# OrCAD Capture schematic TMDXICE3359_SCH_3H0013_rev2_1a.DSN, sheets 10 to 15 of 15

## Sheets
10 P04_AM335x Sheet 2 of 3: size C
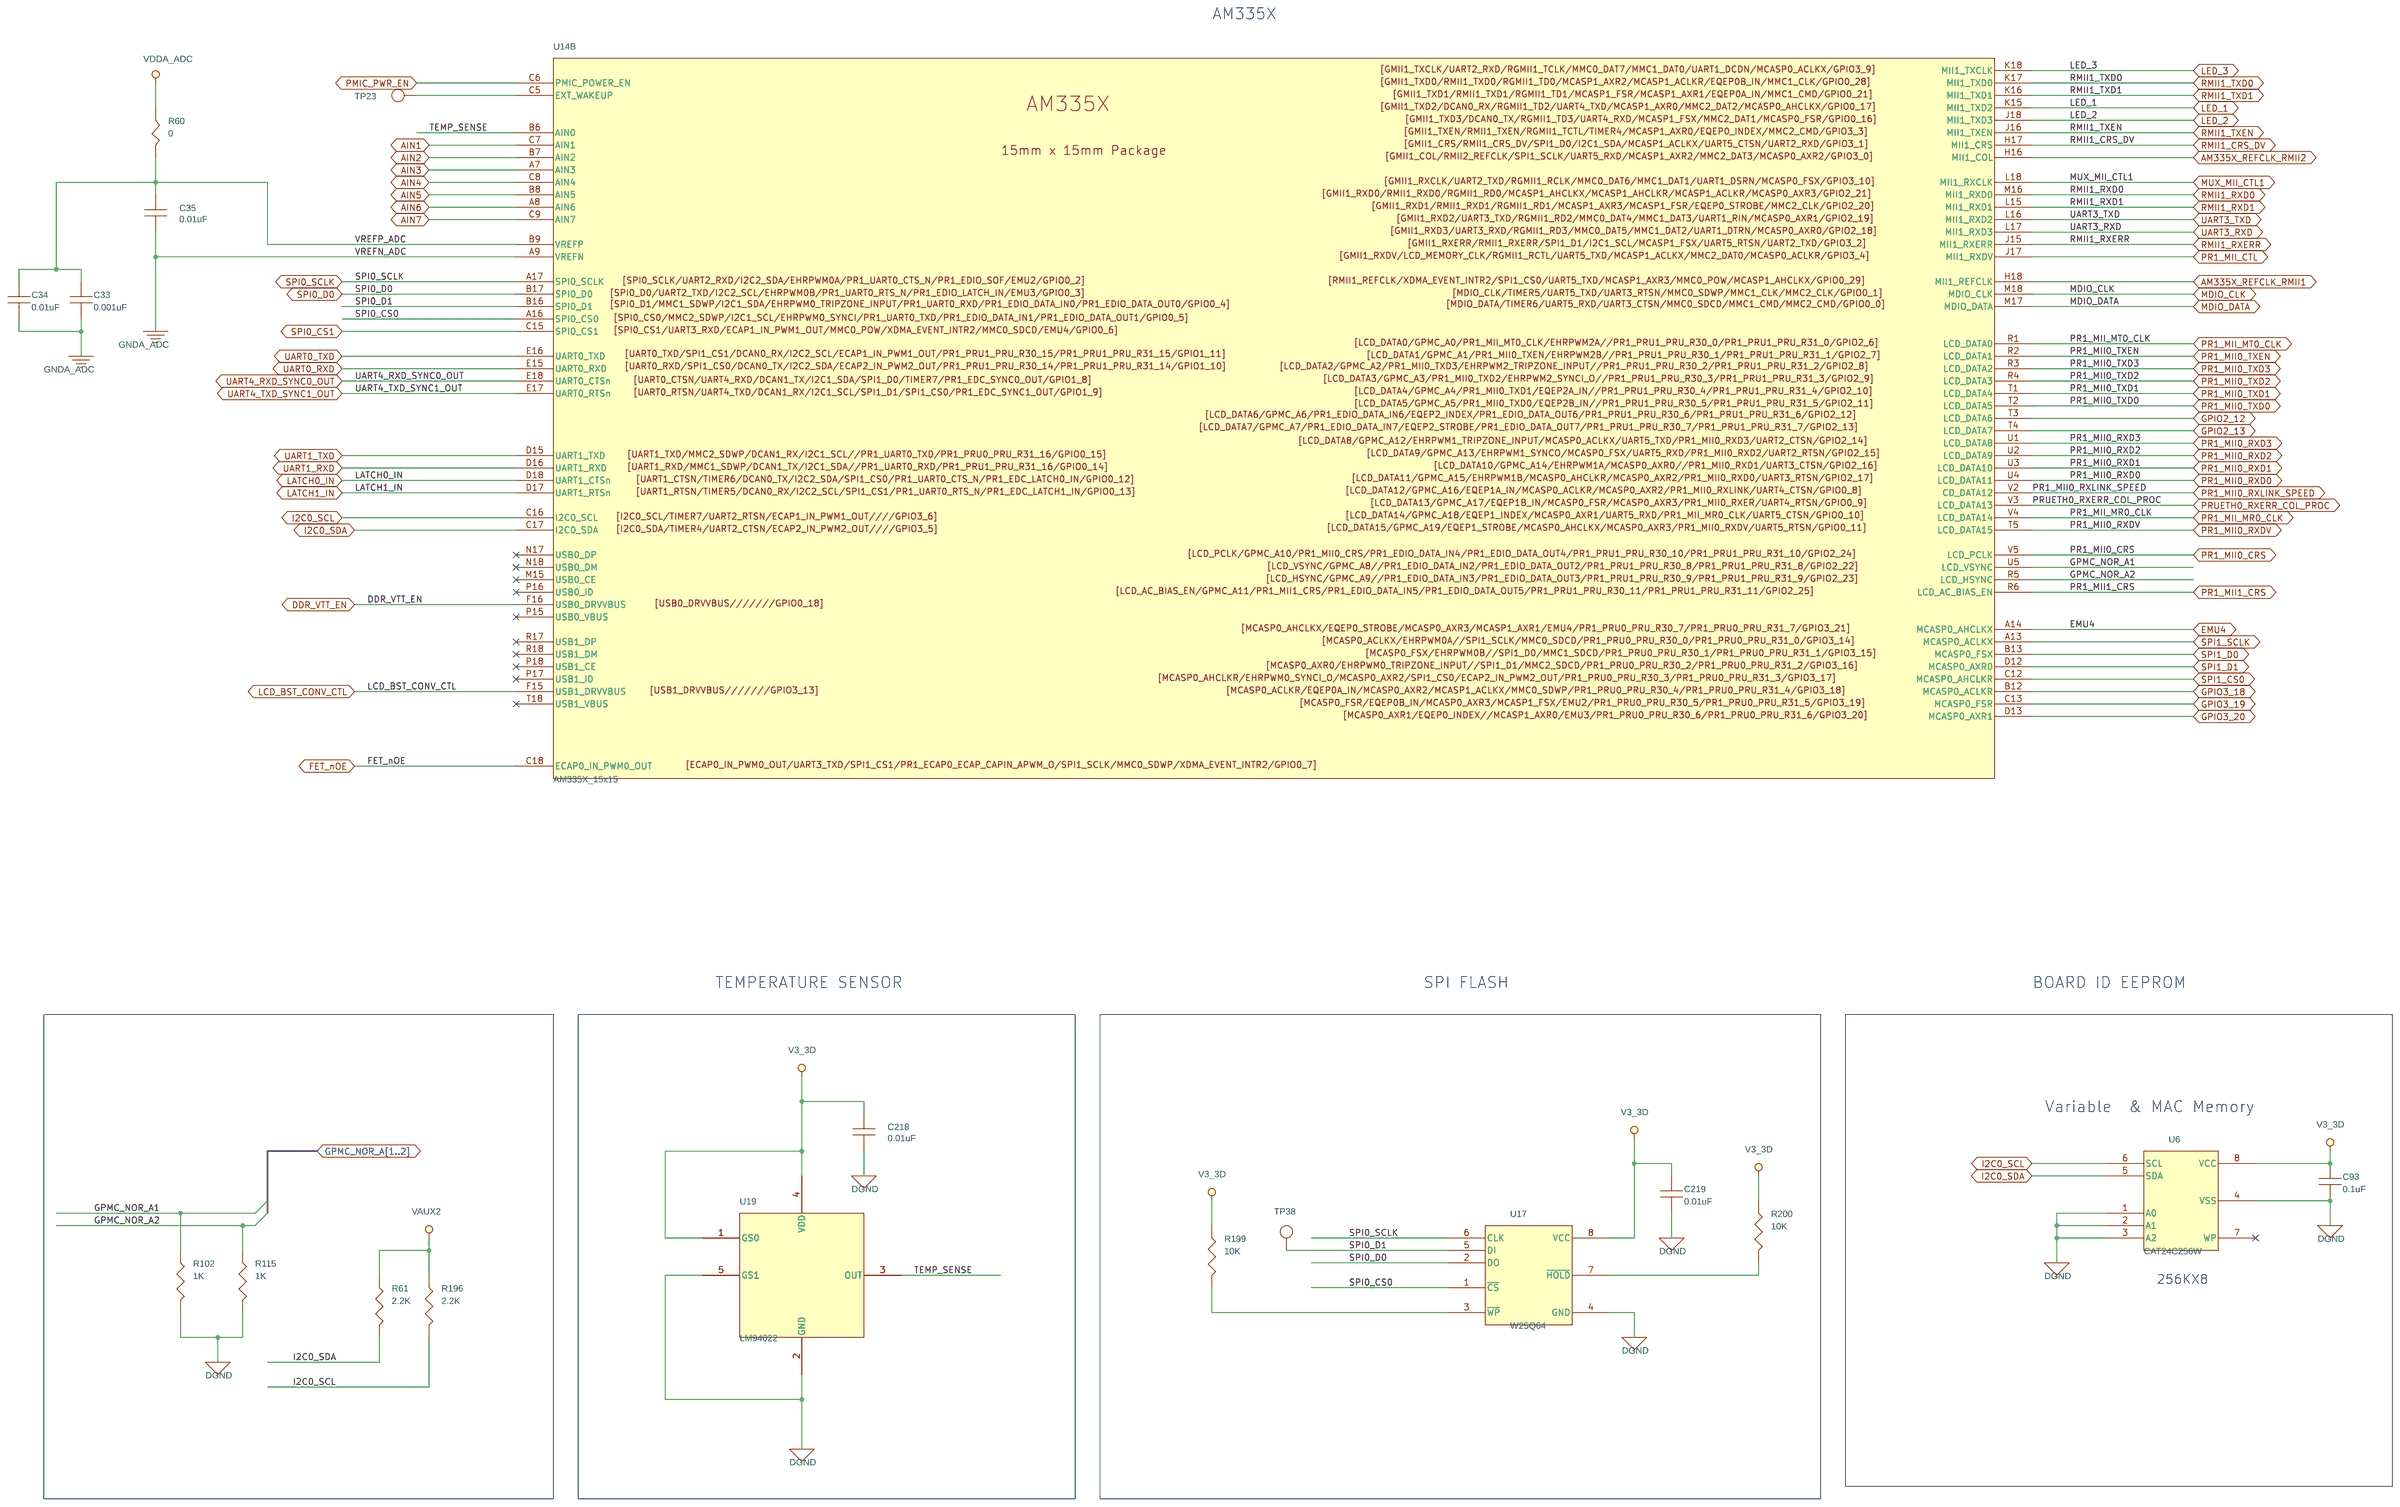
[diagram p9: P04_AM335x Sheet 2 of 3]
11 P03_AM335x Sheet 1 of 3: size C
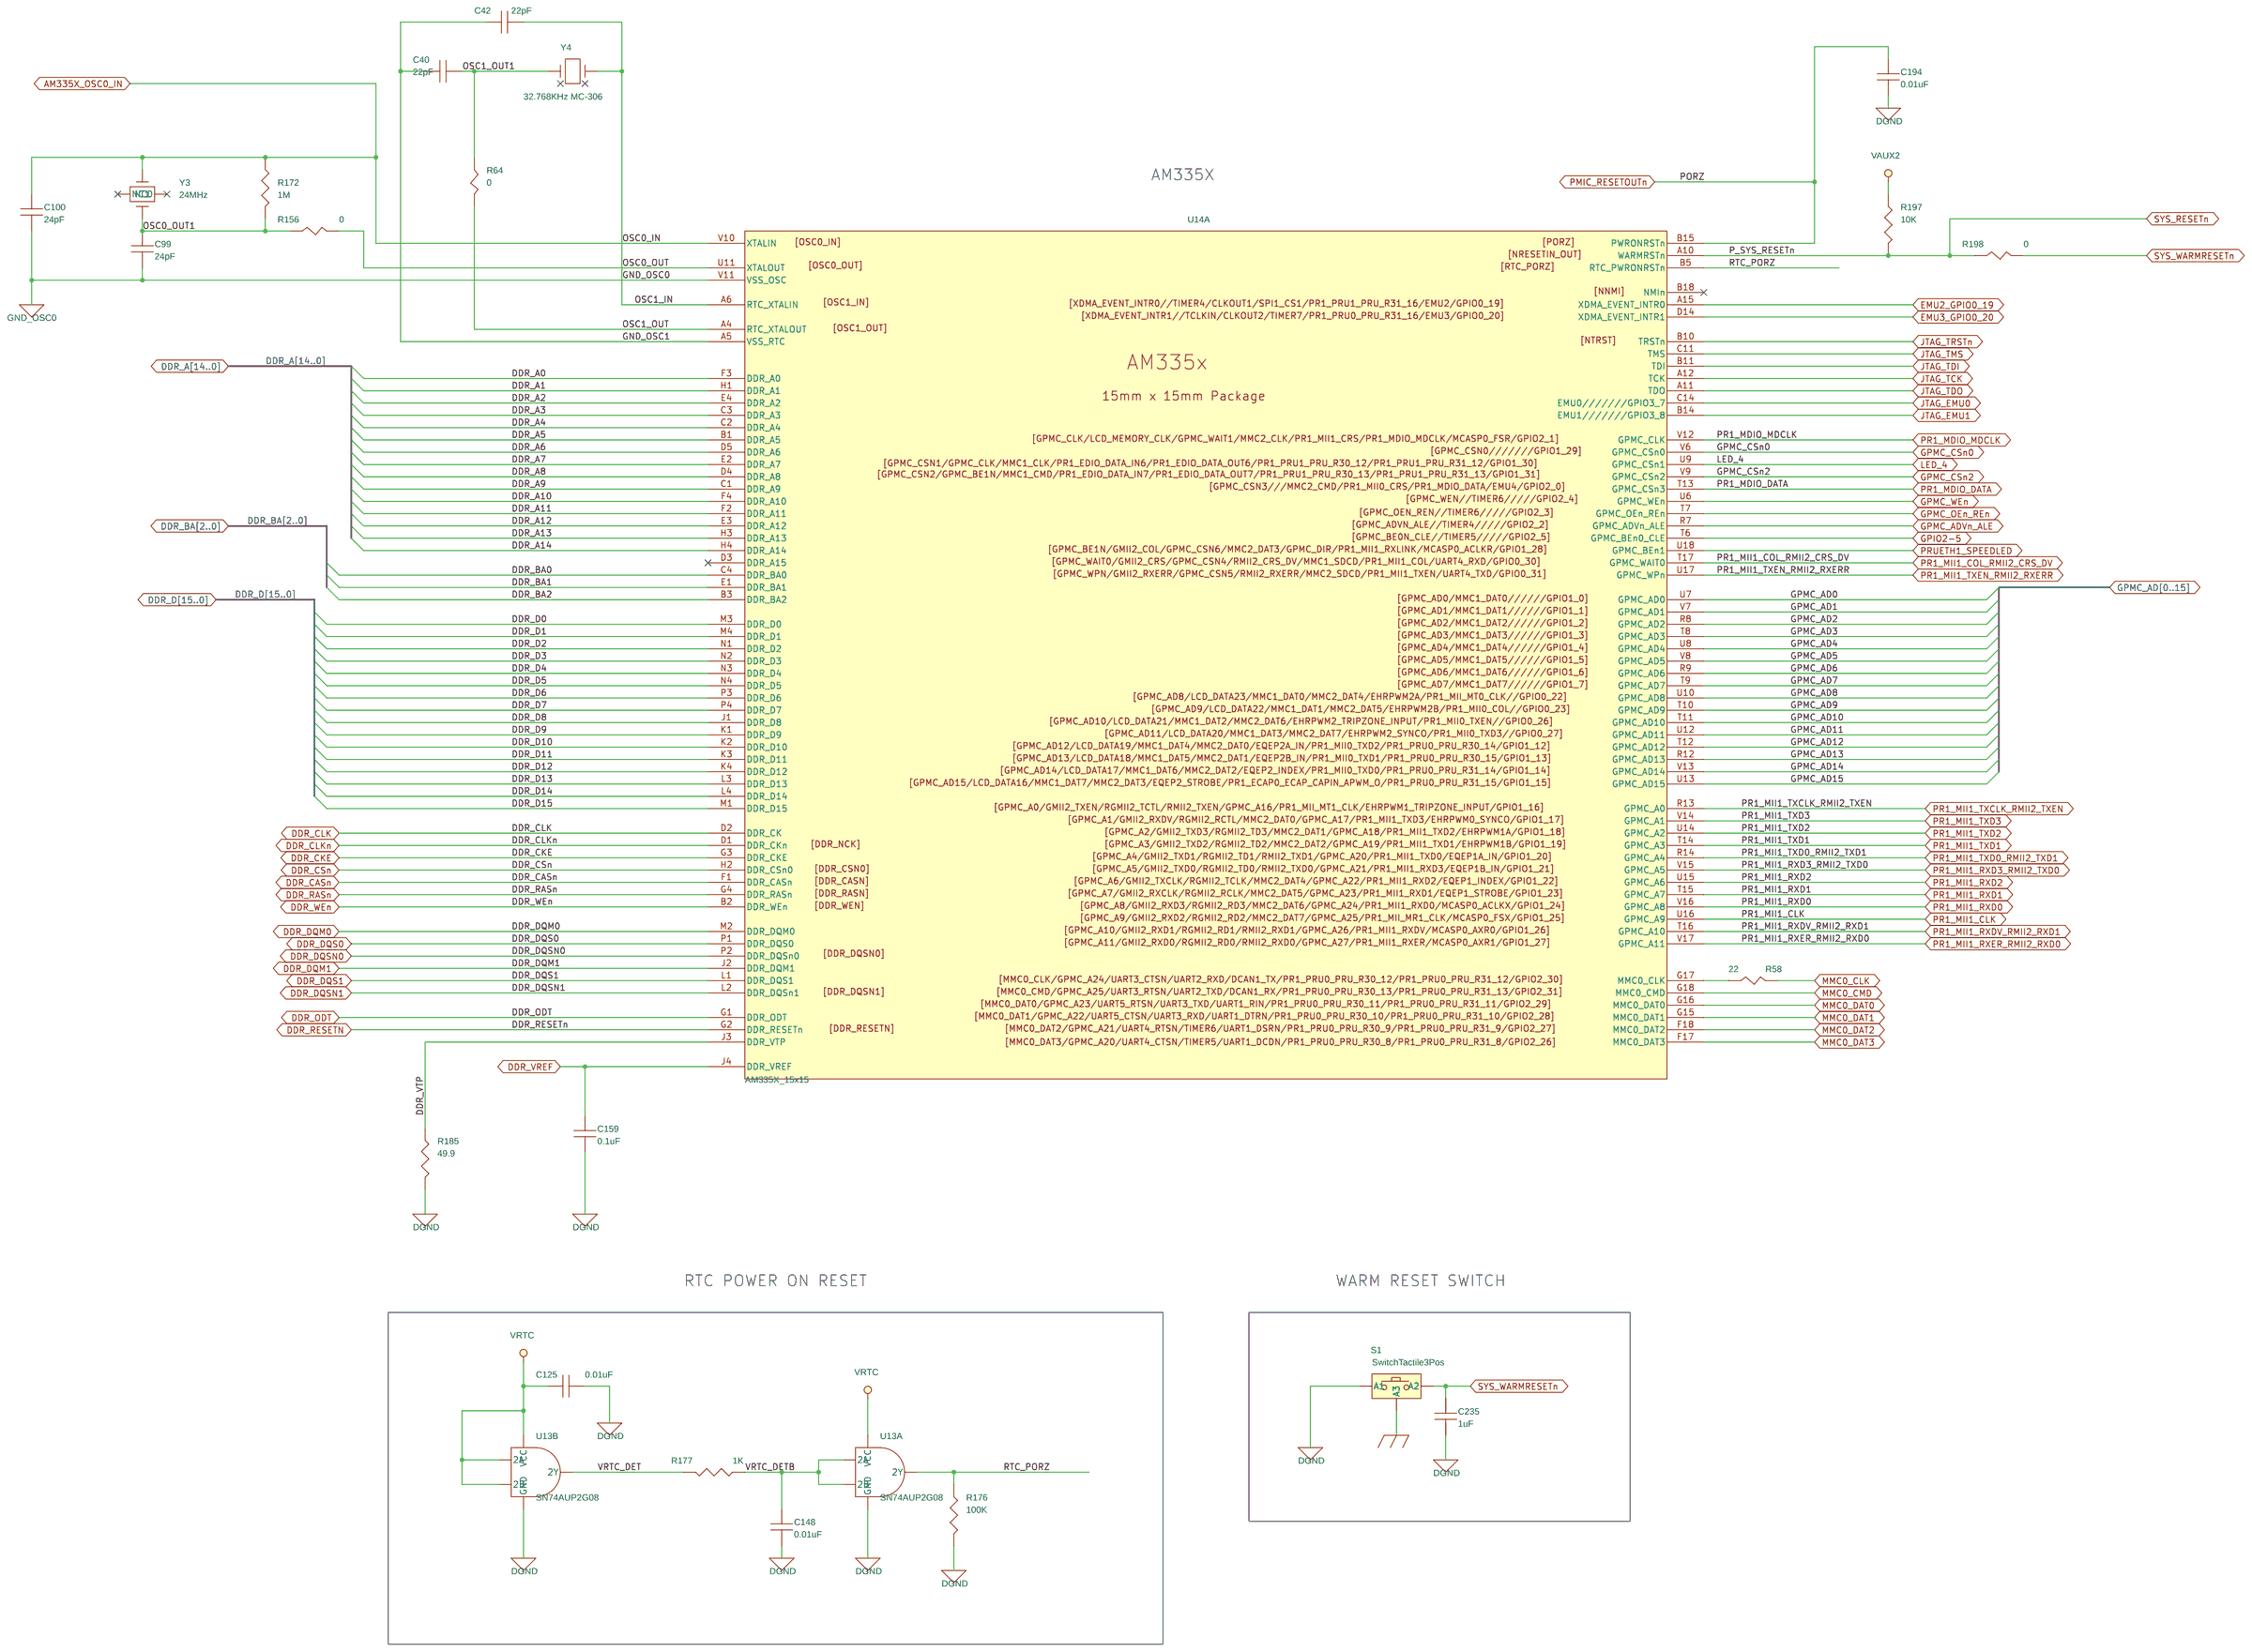
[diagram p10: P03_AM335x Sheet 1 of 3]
12 P02_Power Management: size C
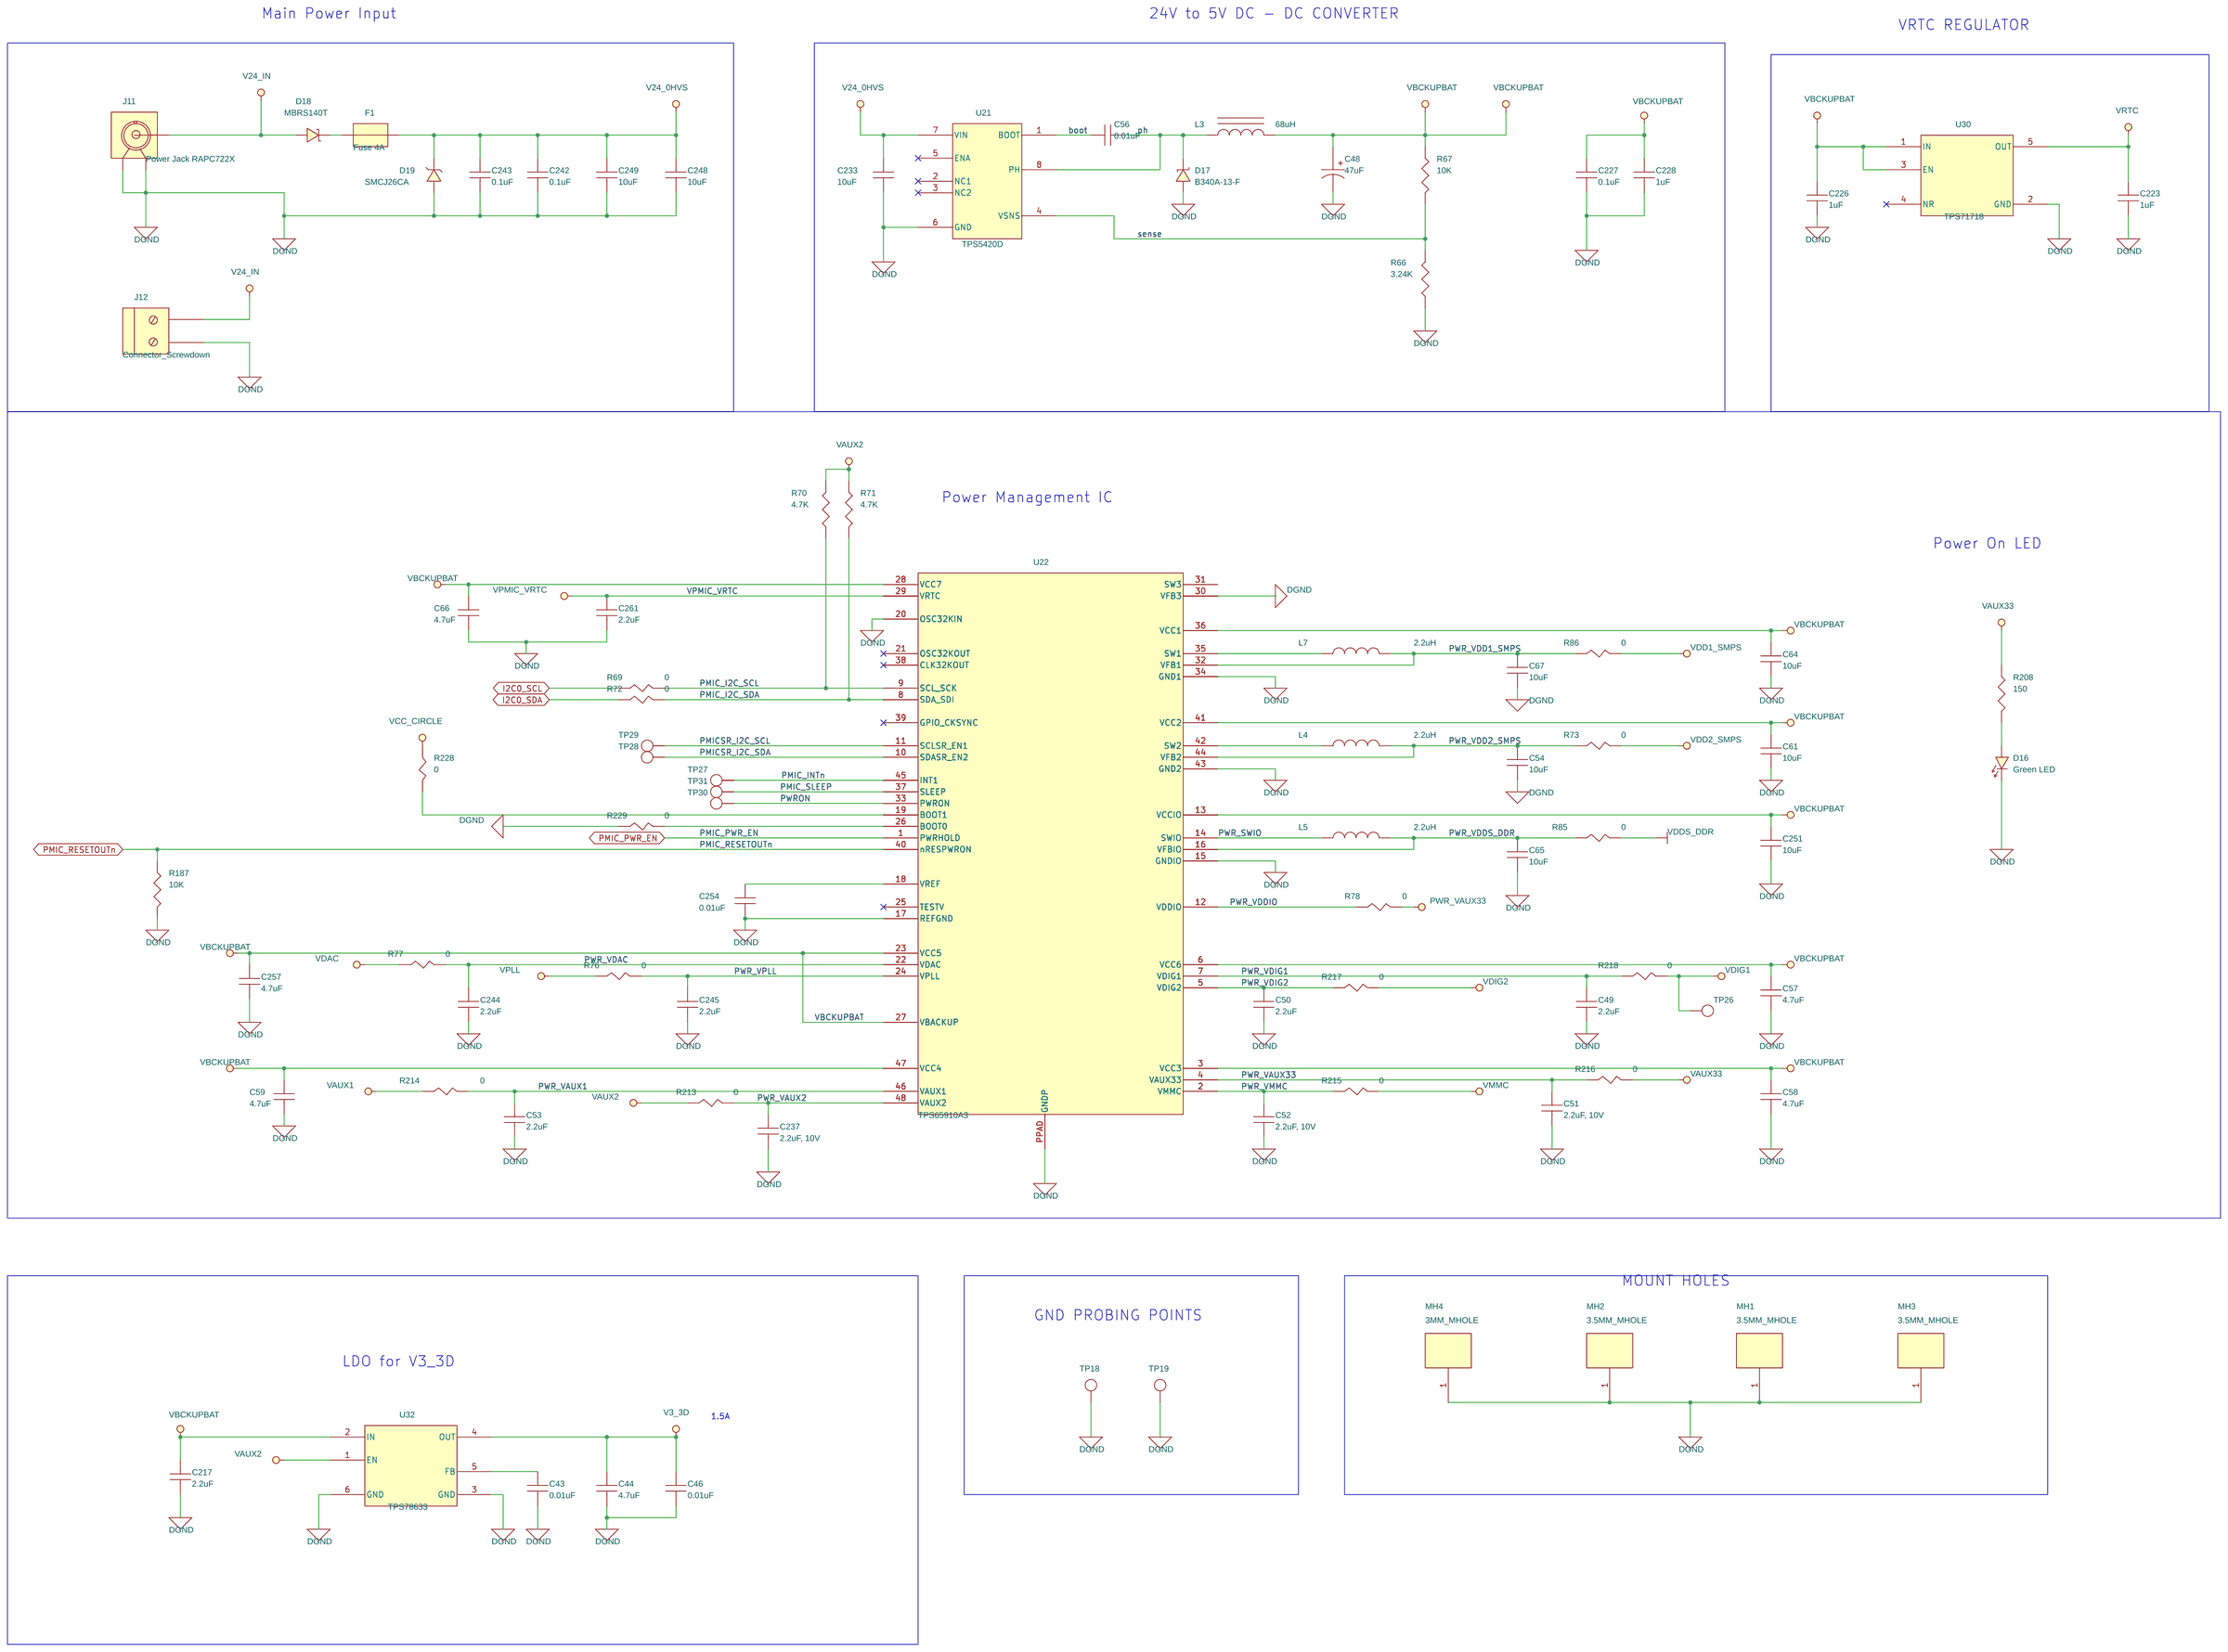
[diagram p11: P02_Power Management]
13 P01_Title Page
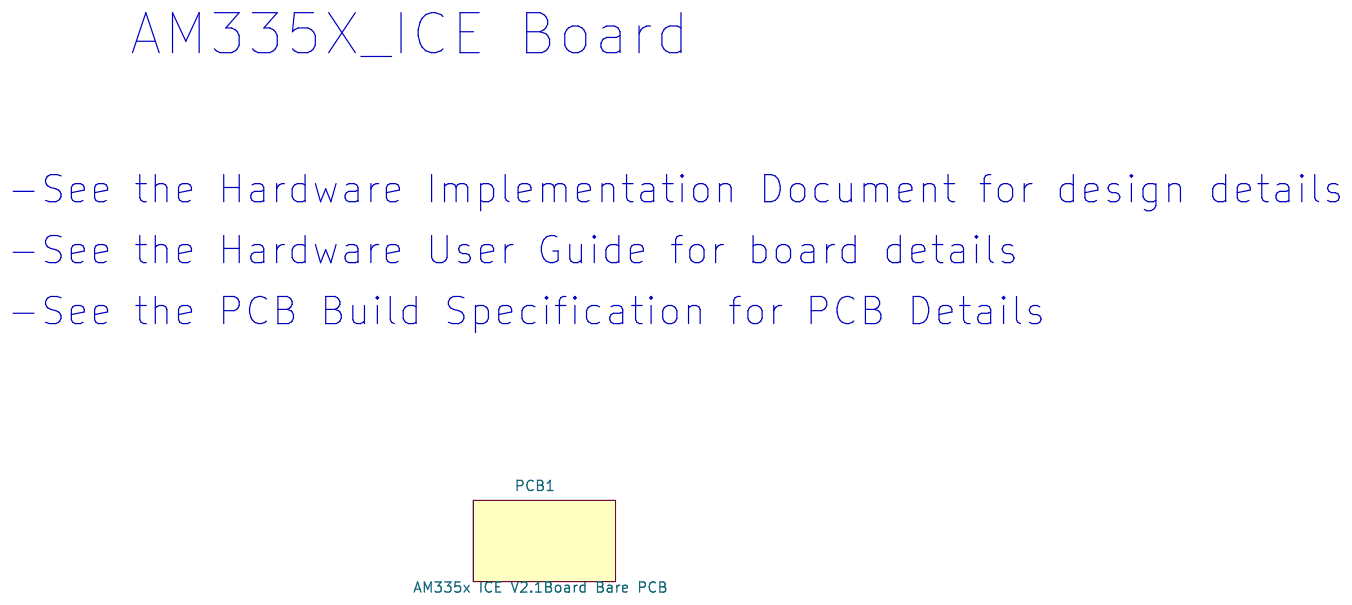
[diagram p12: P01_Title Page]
14 P15_USB_TO_UART/ JTAG: size C
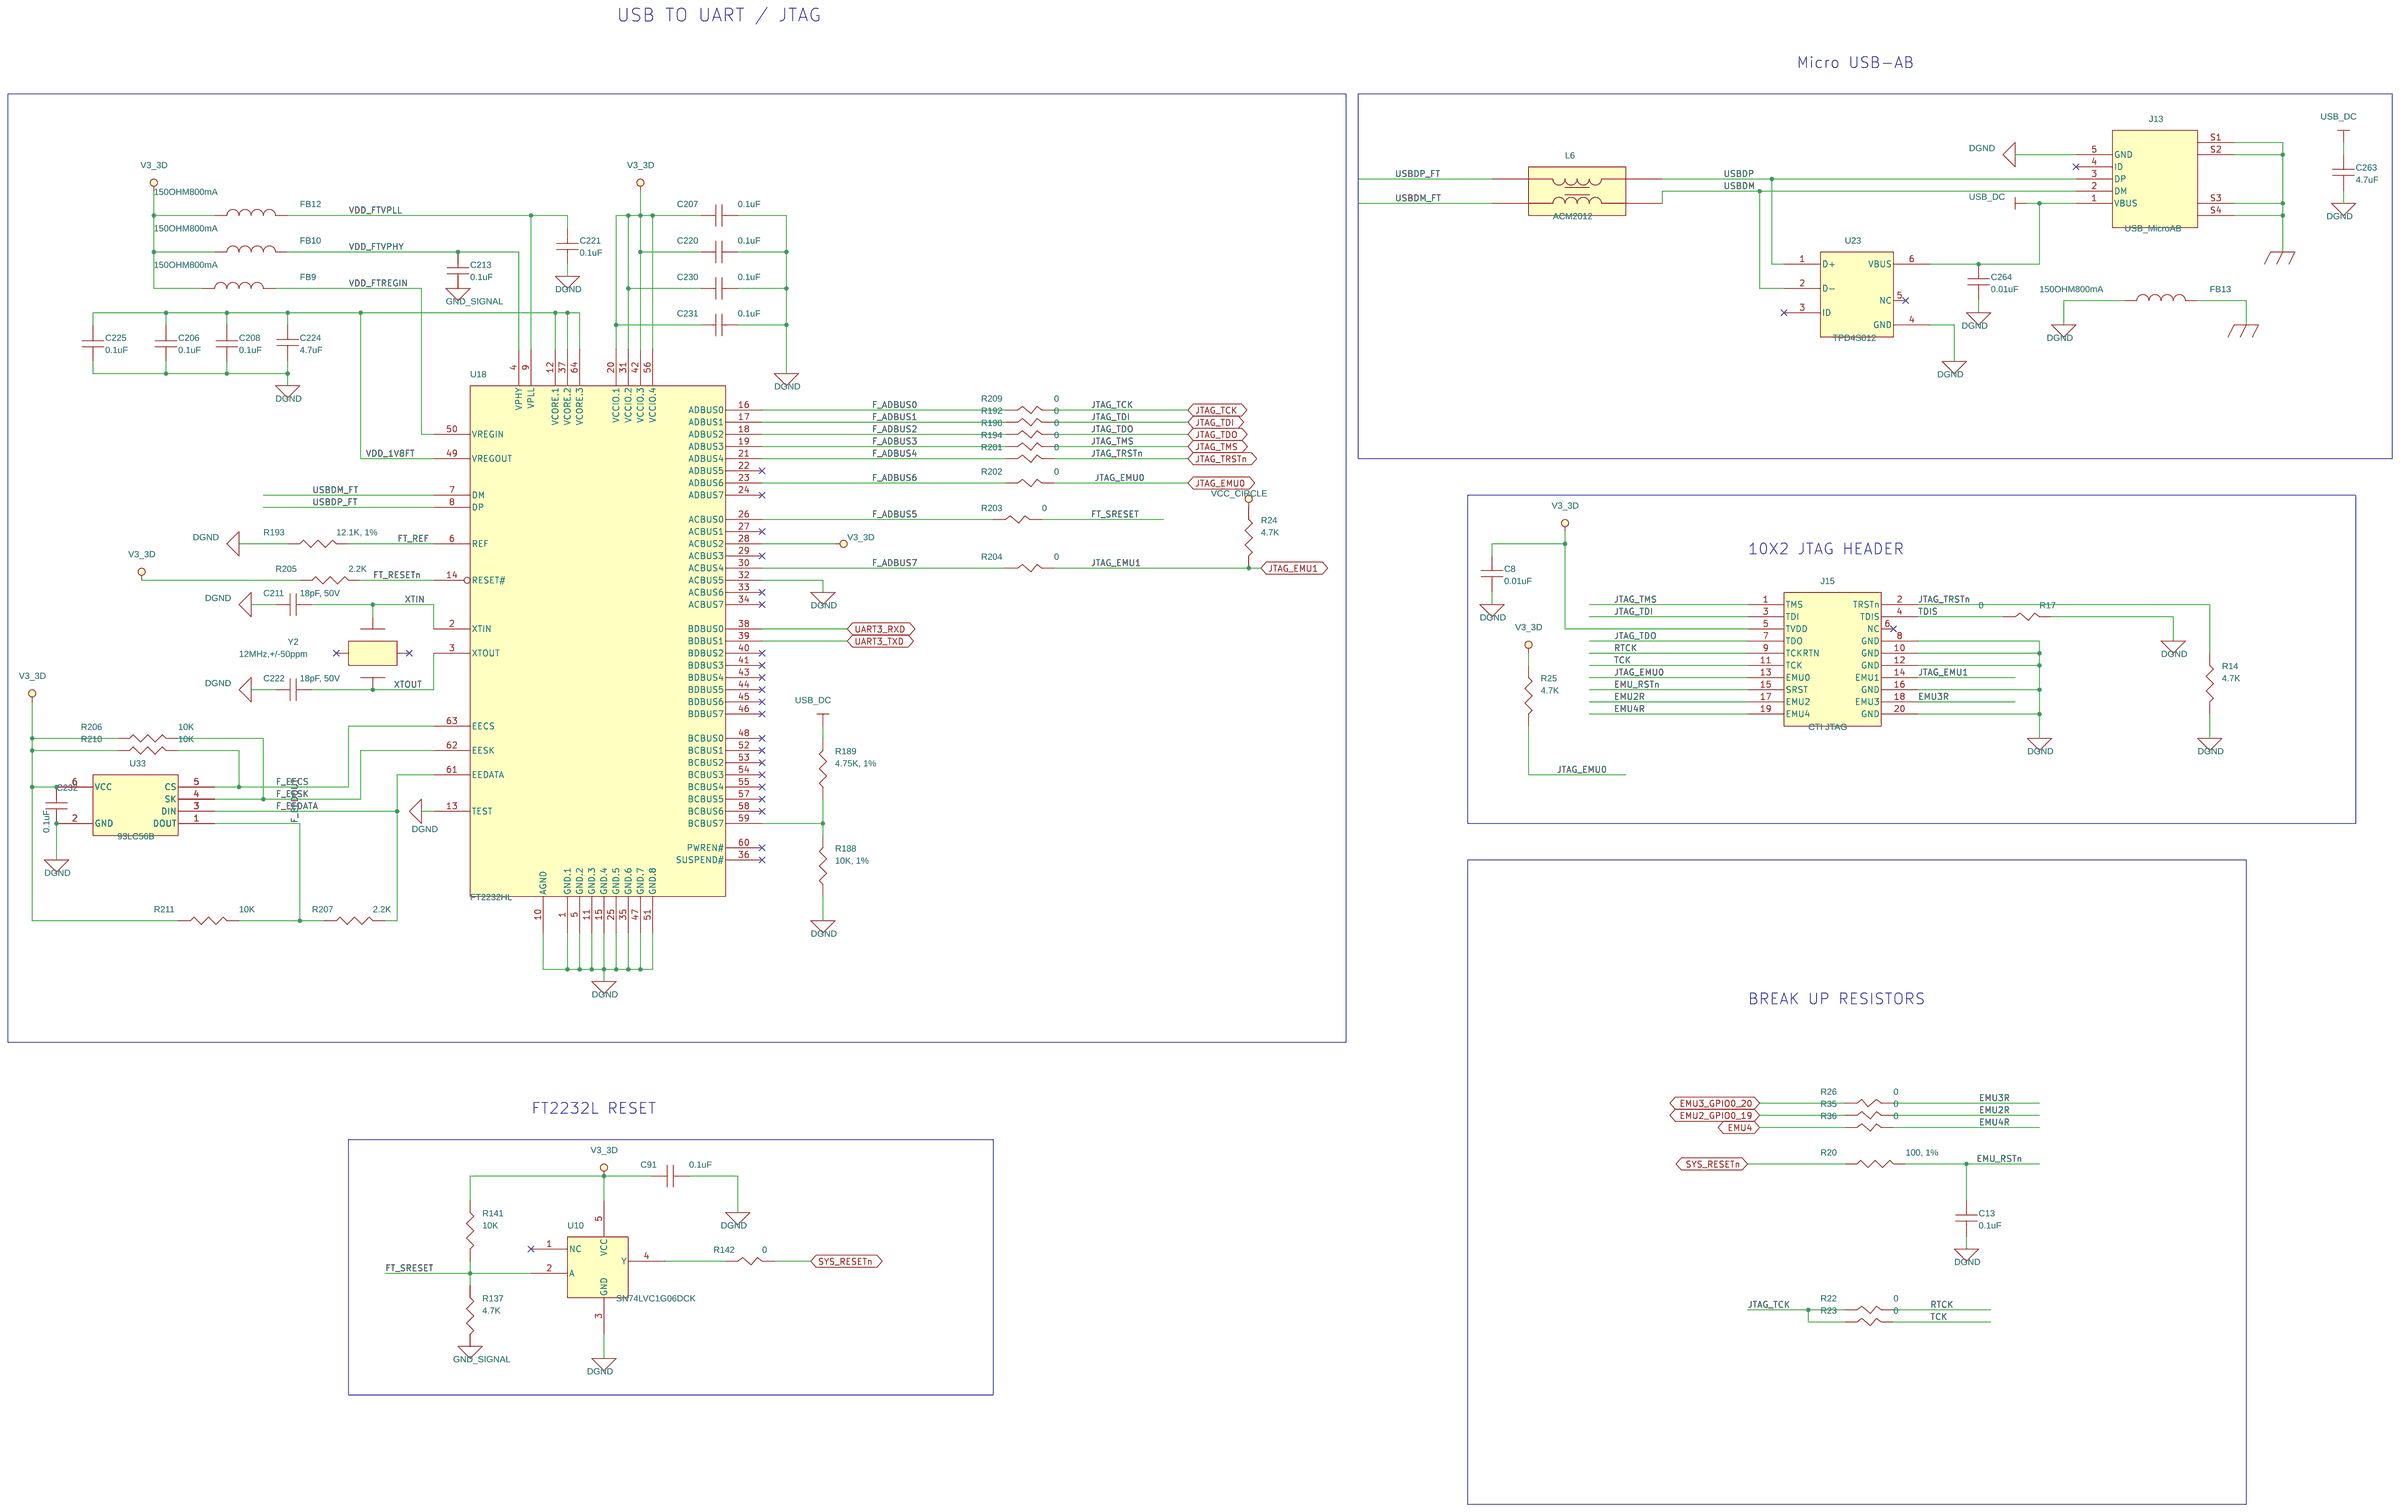
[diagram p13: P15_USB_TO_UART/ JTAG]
15 P14_Industrial I/O: size C
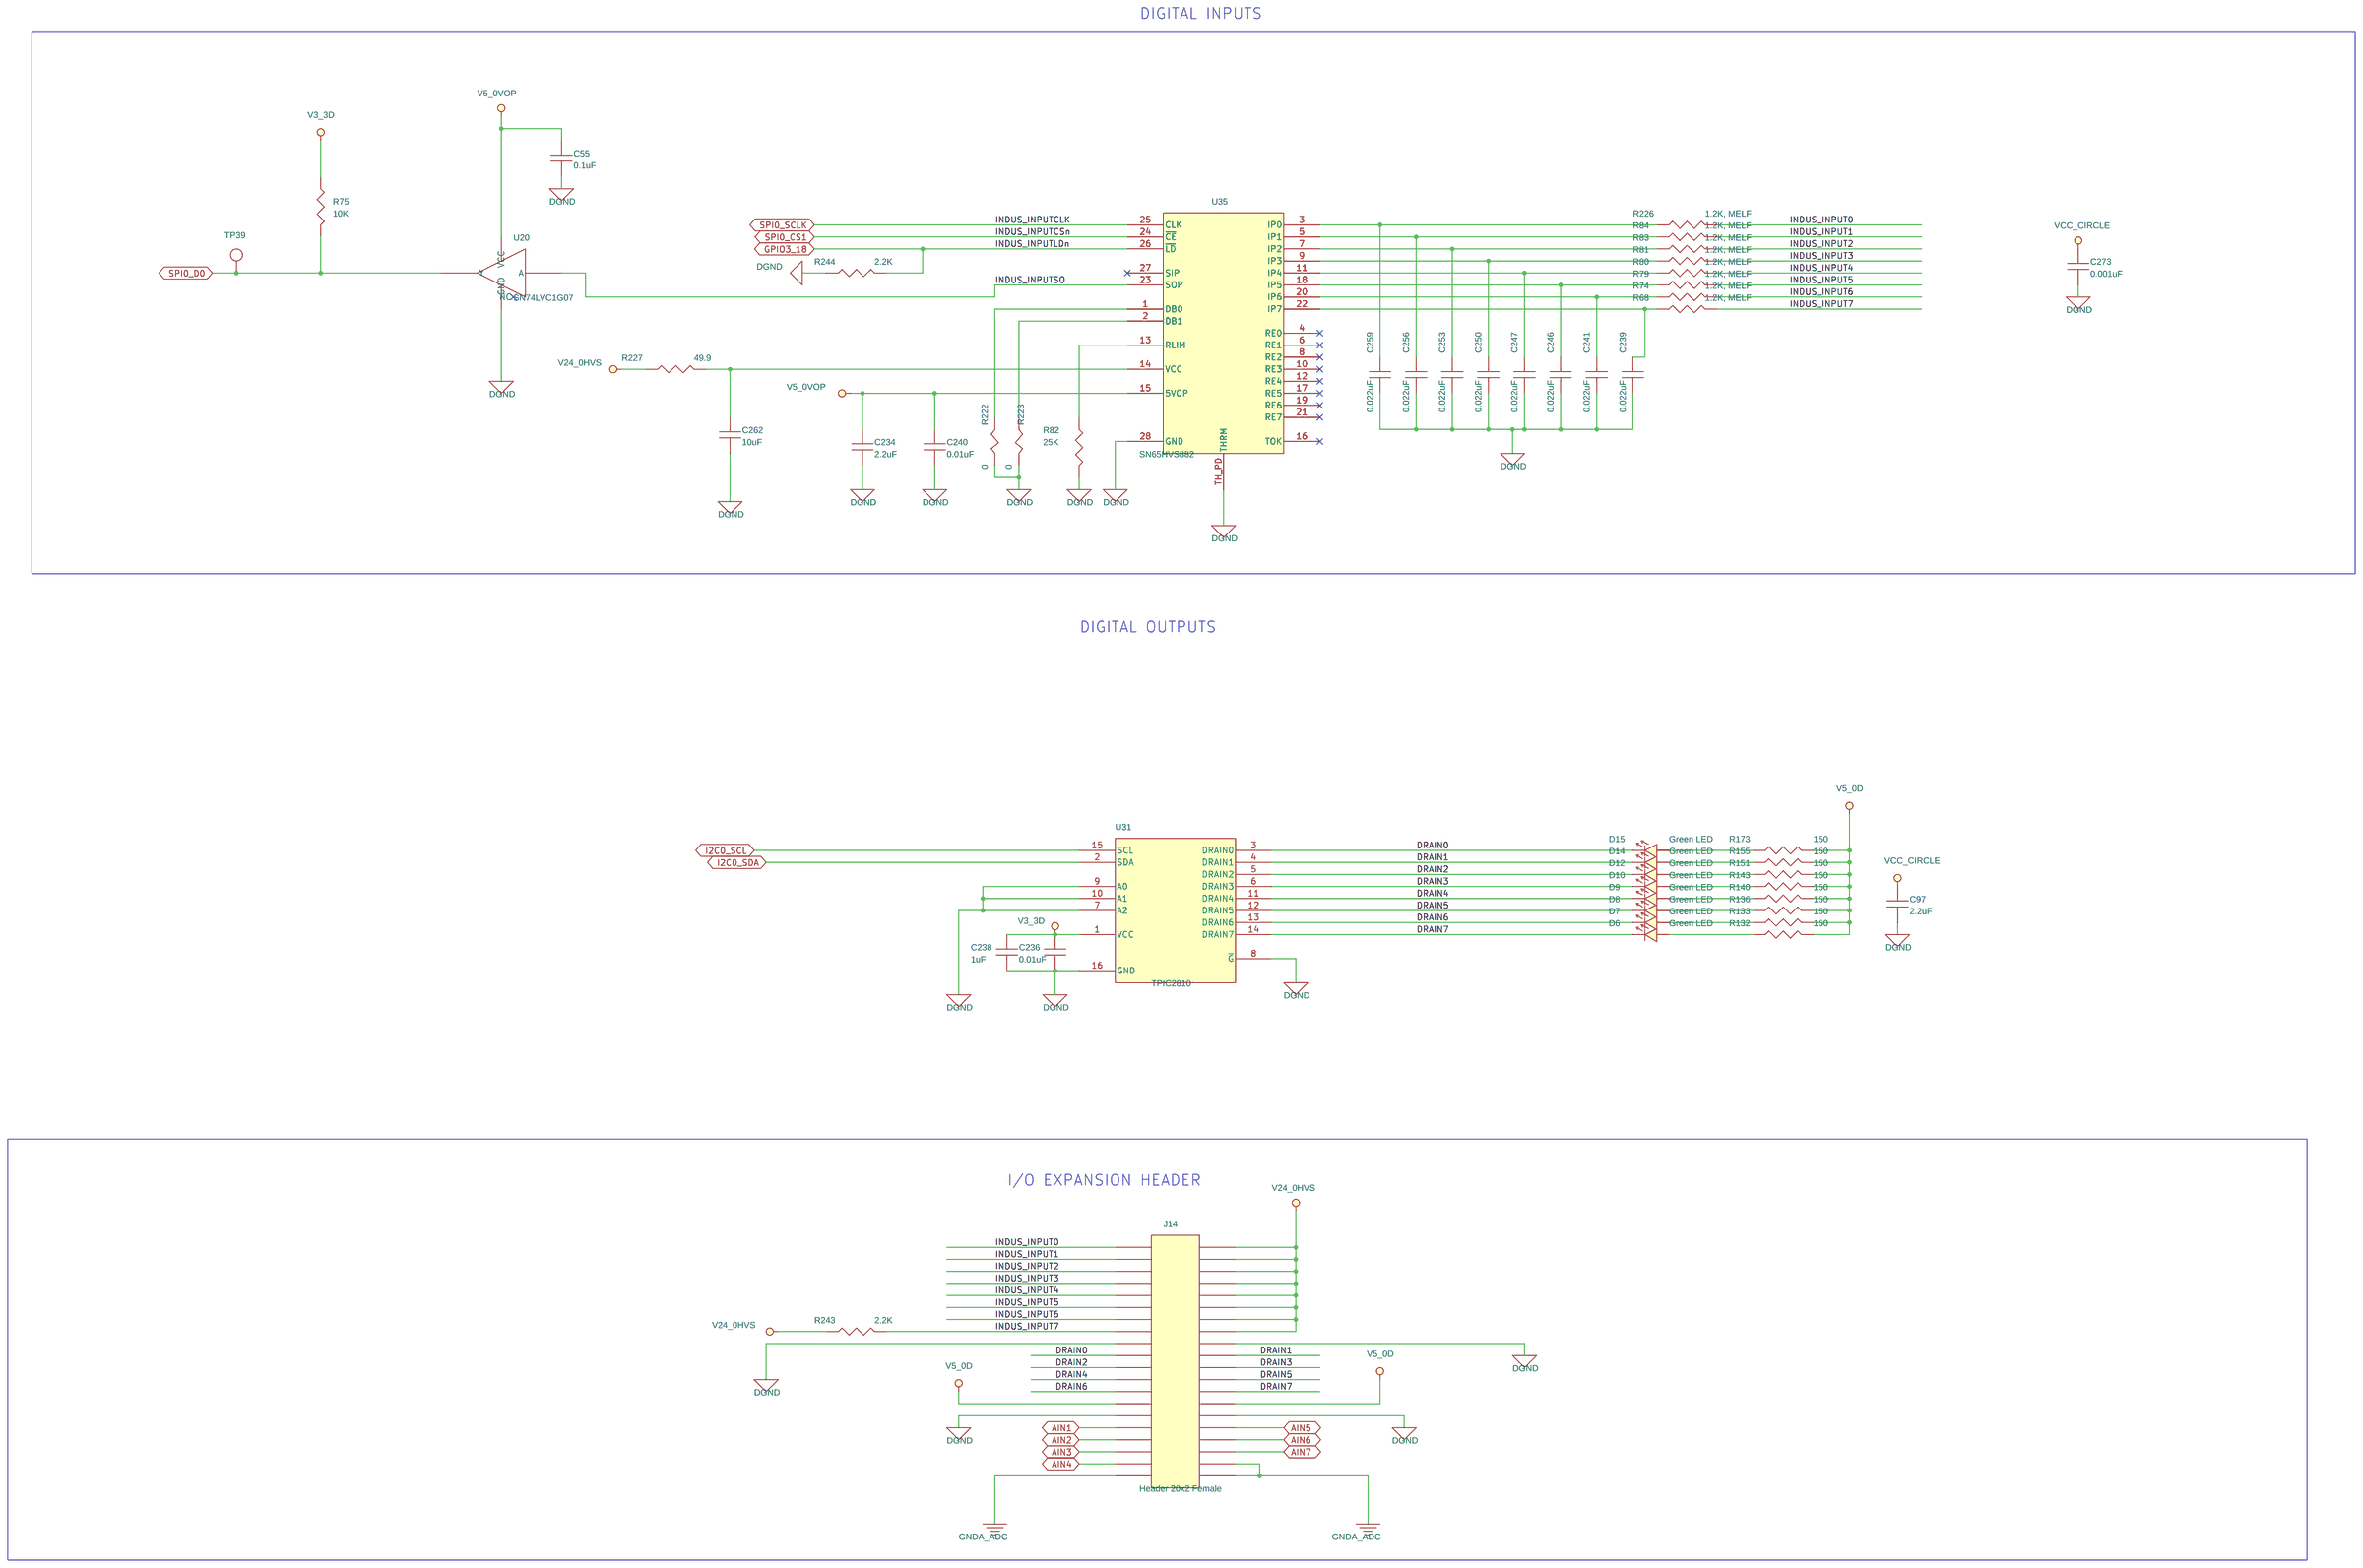
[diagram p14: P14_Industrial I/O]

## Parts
sheet P01_Title Page
PCB1  AM335x ICE V2.1Board Bare PCB  [DNP]
sheet P02_Power Management
C43  0.01uF  [SM-7351-CAP-0402]
C44  4.7uF  [SM-7351-CAP-0603]
C46  0.01uF  [SM-7351-CAP-0402]
C48  47uF  [7343]
C49  2.2uF  [SM-7351-CAP-0402]
C50  2.2uF  [SM-7351-CAP-0402]
C51  2.2uF, 10V  [SM-7351-CAP-0402]
C52  2.2uF, 10V  [SM-7351-CAP-0402]
C53  2.2uF  [SM-7351-CAP-0402]
C54  10uF  [SM-7351-CAP-0805]
C56  0.01uF  [SM-7351-CAP-0402]
C57  4.7uF  [SM-7351-CAP-0603]
C58  4.7uF  [SM-7351-CAP-0603]
C59  4.7uF  [SM-7351-CAP-0603]
C61  10uF  [SM-7351-CAP-0805]
C64  10uF  [SM-7351-CAP-0805]
C65  10uF  [SM-7351-CAP-0805]
C66  4.7uF  [SM-7351-CAP-0603]
C67  10uF  [SM-7351-CAP-0805]
C217  2.2uF  [SM-7351-CAP-0805]
C223  1uF  [SM-7351-CAP-0402]
C226  1uF  [SM-7351-CAP-0402]
C227  0.1uF  [SM-7351-CAP-0402]
C228  1uF  [SM-7351-CAP-0402]
C233  10uF  [SM-7351-CAP-1206]
C237  2.2uF, 10V  [SM-7351-CAP-0402]
C242  0.1uF  [SM-7351-CAP-0402]
C243  0.1uF  [SM-7351-CAP-0402]
C244  2.2uF  [SM-7351-CAP-0402]
C245  2.2uF  [SM-7351-CAP-0402]
C248  10uF  [SM-7351-CAP-1206]
C249  10uF  [SM-7351-CAP-1206]
C251  10uF  [SM-7351-CAP-0805]
C254  0.01uF  [SM-7351-CAP-0402]
C257  4.7uF  [SM-7351-CAP-0603]
C261  2.2uF  [SM-7351-CAP-0402]
D16  Green LED  [sm_led_0805]
D17  B340A-13-F  [DO157LS_116X220SMA]
D18  MBRS140T  [mbrs140t]
D19  SMCJ26CA  [SMCJ36CA]
F1  Fuse 4A  [smdfuseblk]
J11  Power Jack RAPC722X  [CNRAPC722]
J12  Connector_Screwdown  [conn_osttc02]
L3  68uH  [IND_354SMD_400SQ]
L4  2.2uH  [VLCF5020T]
L5  2.2uH  [VLCF5020T]
L7  2.2uH  [VLCF5020T]
MH1  3.5MM_MHOLE  [MH163X138PL]
MH2  3.5MM_MHOLE  [MH163X138PL]
MH3  3.5MM_MHOLE  [MH163X138PL]
MH4  3MM_MHOLE  [MH163X138PL]
R66  3.24K  [SM-7351-RES-0402]
R67  10K  [SM-7351-RES-0402]
R69  0  [SM-7351-RES-0402]
R70  4.7K  [SM-7351-RES-0402]
R71  4.7K  [SM-7351-RES-0402]
R72  0  [SM-7351-RES-0402]
R73  0  [SM-7351-RES-0603]
R76  0  [SM-7351-RES-0603]
R77  0  [SM-7351-RES-0603]
R78  0  [SM-7351-RES-0603]
R85  0  [SM-7351-RES-0603]
R86  0  [SM-7351-RES-0603]
R187  10K  [SM-7351-RES-0402]
R208  150  [SM-7351-RES-0402]
R213  0  [SM-7351-RES-0603]
R214  0  [SM-7351-RES-0603]
R215  0  [SM-7351-RES-0603]
R216  0  [SM-7351-RES-0603]
R217  0  [SM-7351-RES-0603]
R218  0  [SM-7351-RES-0603]
R228  0  [SM-7351-RES-0402]
R229  0  [SM-7351-RES-0402]
TP18  TP  [TH_TP_5002]
TP19  TP  [TH_TP_5002]
TP26  TP1mm  [tp_smd1mmcircle]
TP27  TP1mm  [tp_smd1mmcircle]
TP28  TP1mm  [tp_smd1mmcircle]
TP29  TP1mm  [tp_smd1mmcircle]
TP30  TP1mm  [tp_smd1mmcircle]
TP31  TP1mm  [tp_smd1mmcircle]
U21  TPS5420D  [SOIC-8]
U22  TPS65910A3  [U_48_RSL]
U30  TPS71718  [smdsc70-5]
U32  TPS78633  [sot223_6pin]
sheet P03_AM335x Sheet 1 of 3
C40  22pF  [SM-7351-CAP-0402]
C42  22pF  [SM-7351-CAP-0402]
C99  24pF  [SM-7351-CAP-0402]
C100  24pF  [SM-7351-CAP-0402]
C125  0.01uF  [SM-7351-CAP-0402]
C148  0.01uF  [SM-7351-CAP-0402]
C159  0.1uF  [SM-7351-CAP-0402]
C194  0.01uF  [SM-7351-CAP-0402]
C235  1uF  [SM-7351-CAP-0402]
R58  22  [SM-7351-RES-0402]
R64  0  [SM-7351-RES-0402]
R156  0  [SM-7351-RES-0402]
R172  1M  [SM-7351-RES-0402]
R176  100K  [SM-7351-RES-0402]
R177  1K  [SM-7351-RES-0402]
R185  49.9  [SM-7351-RES-0402]
R197  10K  [SM-7351-RES-0402]
R198  0  [SM-7351-RES-0402]
S1  SwitchTactile3Pos  [SW3_4X2P5]
U13  SN74AUP2G08  [U_8_DCU]  (sections A,B)
Y3  24MHz  [XTAL4_3P2X2P5_SMD]
Y4  32.768KHz MC-306  [MC-306]
sheet P04_AM335x Sheet 2 of 3
C33  0.001uF  [SM-7351-CAP-0402]
C34  0.01uF  [SM-7351-CAP-0402]
C35  0.01uF  [SM-7351-CAP-0402]
C93  0.1uF  [SM-7351-CAP-0402]
C218  0.01uF  [SM-7351-CAP-0402]
C219  0.01uF  [SM-7351-CAP-0402]
R60  0  [SM-7351-RES-0402]
R61  2.2K  [sm-7351-res-0402]
R102  1K  [SM-7351-RES-0402]
R115  1K  [SM-7351-RES-0402]
R196  2.2K  [sm-7351-res-0402]
R199  10K  [SM-7351-RES-0402]
R200  10K  [SM-7351-RES-0402]
TP23  TP1mm  [tp_smd1mmcircle]
TP38  TP1mm  [tp_smd1mmcircle]
U6  CAT24C256W  [soic8_208]
U17  W25Q64  [SOIC8_265]
U19  LM94022  [SC70-5]
sheet P05_AM335x Page 3 of 3
U14  AM335X_15x15  [am33xx_15x15]  (sections A,B,C)
sheet P14_Industrial I/O
C55  0.1uF  [SM-7351-CAP-0402]
C97  2.2uF  [SM-7351-CAP-0805]
C234  2.2uF  [SM-7351-CAP-0805]
C236  0.01uF  [SM-7351-CAP-0402]
C238  1uF  [SM-7351-CAP-0402]
C239  0.022uF  [SM-7351-CAP-0402]
C240  0.01uF  [SM-7351-CAP-0402]
C241  0.022uF  [SM-7351-CAP-0402]
C246  0.022uF  [SM-7351-CAP-0402]
C247  0.022uF  [SM-7351-CAP-0402]
C250  0.022uF  [SM-7351-CAP-0402]
C253  0.022uF  [SM-7351-CAP-0402]
C256  0.022uF  [SM-7351-CAP-0402]
C259  0.022uF  [SM-7351-CAP-0402]
C262  10uF  [SM-7351-CAP-1206]
C273  0.001uF  [SM-7351-CAP-0402]
D6  Green LED  [sm_led_0805]
D7  Green LED  [sm_led_0805]
D8  Green LED  [sm_led_0805]
D9  Green LED  [sm_led_0805]
D10  Green LED  [sm_led_0805]
D12  Green LED  [sm_led_0805]
D14  Green LED  [sm_led_0805]
D15  Green LED  [sm_led_0805]
J14  Header 20x2 Female  [HDR2X20-335M]
R68  1.2K, MELF  [smd_melf0102]
R74  1.2K, MELF  [smd_melf0102]
R75  10K  [SM-7351-RES-0402]
R79  1.2K, MELF  [smd_melf0102]
R80  1.2K, MELF  [smd_melf0102]
R81  1.2K, MELF  [smd_melf0102]
R82  25K  [SM-7351-RES-0603]
R83  1.2K, MELF  [smd_melf0102]
R84  1.2K, MELF  [smd_melf0102]
R132  150  [SM-7351-RES-0402]
R133  150  [SM-7351-RES-0402]
R136  150  [SM-7351-RES-0402]
R140  150  [SM-7351-RES-0402]
R143  150  [SM-7351-RES-0402]
R151  150  [SM-7351-RES-0402]
R155  150  [SM-7351-RES-0402]
R173  150  [SM-7351-RES-0402]
R222  0  [SM-7351-RES-0402]
R223  0  [SM-7351-RES-0402]
R226  1.2K, MELF  [smd_melf0102]
R227  49.9  [smd_melf0102]
R243  2.2K  [sm-7351-res-0402]
R244  2.2K  [sm-7351-res-0402]
TP39  TP1mm  [tp_smd1mmcircle]
U20  SN74LVC1G07  [DCK5]
U31  TPIC2810  [u_16_d]
U35  SN65HVS882  [u_28_pwp]
sheet P15_USB_TO_UART/ JTAG
C8  0.01uF  [SM-7351-CAP-0402]
C13  0.1uF  [SM-7351-CAP-0402]
C91  0.1uF  [SM-7351-CAP-0402]
C206  0.1uF  [SM-7351-CAP-0402]
C207  0.1uF  [SM-7351-CAP-0402]
C208  0.1uF  [SM-7351-CAP-0402]
C211  18pF, 50V  [SM-7351-CAP-0402]
C213  0.1uF  [SM-7351-CAP-0402]
C220  0.1uF  [SM-7351-CAP-0402]
C221  0.1uF  [SM-7351-CAP-0402]
C222  18pF, 50V  [SM-7351-CAP-0402]
C224  4.7uF  [SM-7351-CAP-0603]
C225  0.1uF  [SM-7351-CAP-0402]
C230  0.1uF  [SM-7351-CAP-0402]
C231  0.1uF  [SM-7351-CAP-0402]
C232  0.1uF  [SM-7351-CAP-0402]
C263  4.7uF  [SM-7351-CAP-0603]
C264  0.01uF  [SM-7351-CAP-0402]
FB9  150OHM800mA  [sm-7351-ind-0805]
FB10  150OHM800mA  [sm-7351-ind-0805]
FB12  150OHM800mA  [sm-7351-ind-0805]
FB13  150OHM800mA  [sm-7351-ind-0805]
J13  USB_MicroAB  [ZX62-AB-5PA]
J15  CTI JTAG  [header10x2]
L6  ACM2012  [ACM2012H]
R14  4.7K  [SM-7351-RES-0402]
R17  0  [SM-7351-RES-0402]
R20  100, 1%  [SM-7351-RES-0402]
R22  0  [SM-7351-RES-0402]
R23  0  [SM-7351-RES-0402]
R24  4.7K  [SM-7351-RES-0402]
R25  4.7K  [SM-7351-RES-0402]
R26  0  [SM-7351-RES-0402]
R35  0  [SM-7351-RES-0402]
R36  0  [SM-7351-RES-0402]
R137  4.7K  [SM-7351-RES-0402]
R141  10K  [SM-7351-RES-0402]
R142  0  [SM-7351-RES-0402]
R188  10K, 1%  [SM-7351-RES-0402]
R189  4.75K, 1%  [SM-7351-RES-0402]
R190  0  [SM-7351-RES-0402]
R192  0  [SM-7351-RES-0402]
R193  12.1K, 1%  [SM-7351-RES-0402]
R194  0  [SM-7351-RES-0402]
R201  0  [SM-7351-RES-0402]
R202  0  [SM-7351-RES-0402]
R203  0  [SM-7351-RES-0402]
R204  0  [SM-7351-RES-0402]
R205  2.2K  [sm-7351-res-0402]
R206  10K  [SM-7351-RES-0402]
R207  2.2K  [sm-7351-res-0402]
R209  0  [SM-7351-RES-0402]
R210  10K  [SM-7351-RES-0402]
R211  10K  [SM-7351-RES-0402]
U10  SN74LVC1G06DCK  [DCK5]
U18  FT2232HL  [LQFP64_10X10]
U23  TPD4S012  [U_6_DRY]
U33  93LC56B  [SOT23-6]
Y2  12MHz,+/-50ppm  [XTAL4_3P2X5SMD]

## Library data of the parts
PCB1 = AM335xICEV2BoardBarePCB: AM335x  ICE V2.1 EVM PCB Bare; DescriptiveText: AM335x  ICE V2.1 EVM PCB Bare; PartName: AM335xICEV2.1BoardBarePCB
C8 C34 C35 C43 C46 C56 C125 C148 C194 C218 C219 C236 C240 C254 C264 = 0.01uFCapacitor16V10%0402
C44 C57-C59 C66 C257 C263 = 4.7uFCapacitor16V10%0603
C48 = 47uFCapacitor10V10%smd2917
C49 C50 C53 C244 C245 C261 = 2.2uFCapacitor6.3V20%smdX5R0402
C51 C52 C237 = 2.2uFCapacitor10V20%smd0402
C54 C61 C64 C65 C67 C251 = 10uFCapacitor16V10%0805
C97 C217 C234 = 2.2uF16V10%SMD0805
C223 C226 C228 C235 C238 = 1uFCapacitor10V10%0402
C13 C55 C91 C93 C159 C206-C208 C213 C220 C221 C225 C227 C230-C232 = 0.1uFCapacitor16V10%0402
C233 C248 C249 C262 = 10uFCapacitor50V10%1206
C242 C243 = 0.1uFCapacitor50V10%0402
D6-D10 D12 D14-D16 = LED_Green
D17 = Diode_3ARect_rev40V
D18 = Diode_MBRS140T3
D19 = Diode_SMCJ26CA
F1 = Fuse_4A
J11 = Conn_PwrJack_RAPC722
J12 = Conn_LeadScrewDown_2pin
L3 = 68uHInductor20%1.4Asmd
L4 L5 L7 = 2.2uHInductor10%2.6Asmd
MH1-MH4 = Mounthole_3mm
R66 = 3.24KOhmResistor1_10W1%0402
R67 R75 R141 R187 R197 R199 R200 R206 R210 R211 = 10KOhmResistor1_16W0402
R17 R22 R23 R26 R35 R36 R60 R64 R69 R72 R142 R156 R190 R192 R194 R198 R201-R204 R209 R222 R223 R228 R229 = ZeroOhmResistor1_16W0402
R14 R24 R25 R70 R71 R137 = 4.7KOhmResistor1_16W0402
R73 R76-R78 R85 R86 R213-R218 = ZeroOhmResistor1_16W0603
R132 R133 R136 R140 R143 R151 R155 R173 R208 = 150ohm1_16W1%SMD0402
TP18 TP19 = TestPointThroughHole
TP23 TP26-TP31 TP38 TP39 = Testpoint_SMD1mmCircle
U21 = TPS5420D
U22 = TPS65910A3
U30 = TPS71718
U32 = TPS78633DCQ
C40 C42 = 22pFCapacitor50V10%SMD0402
C99 C100 = 24pFCapacitor50V5%SMD0402
R58 = 22OhmResistor1_16W1%0402
R172 = 1MOhmResistor1_16W0402
R176 = 100KOhmResistor1_16W0402
R102 R115 R177 = 1KOhmResistor1_16W0402
R185 = 49.9OhmResistor1_16W0402
S1 = SwitchTactile3pos_smd
U13 = SN74AUP2G08
Y3 = Crystal24MHz18PFsmd
Y4 = Crystal_SMD32_768kHz
C33 C273 = 0.001uFCapacitor50V5%0402
R61 R196 R205 R207 = 2.2KOhmResistor1_16W0402
U6 = CAT24C256W
U17 = W25Q64
U19 = LM94022
U14 = AM335X_15mmx15mm: MfrNum: AM3359ZCZ
C239 C241 C246 C247 C250 C253 C256 C259 = 0.022uFCapacitor16VX7Rsmd0402
J14 = Header20x2_0.1in_Female
R68 R74 R79-R81 R83 R84 R226 = 1.2Kohm1_3W1%SMDMELF0102
R82 = 25Kohm1_10W0.1%smd0603
R227 = 49.9ohm1_3W1%SMDMELF0102
R243 R244 = 1R_2.2KOhmResistor1_16W0402
U20 = SN74LVC1G07
U31 = TPIC2810
U35 = SN65HVS882
C211 C222 = 18pFCapacitor50V5%0402
C224 = 4.7uFCapacitor6.3V20%smdX5R0603
FB9 FB10 FB12 FB13 = FerBead_180ohm200mA
J13 = Conn_MicroUSBAB
J15 = Header10x2_CJTAG
L6 = ACM2012
R20 = 100ohm1_10W1%SMD0402
R188 = 1R_10KOhmResistor1_10W1%0402
R189 = 1R_4.75KohmResistor1_16W1%0402
R193 = 12.1KohmResistor1_16W1%0402
U10 = SN74LVC1G06DCK
U18 = FT2232_0
U23 = TPD4S012
U33 = 93C46B_SSOT23-6
Y2 = Crystal12MHZ_ECS-120-20-30B

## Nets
DGND: C8.2 C13.2 C43.2 C44.2 C46.2 C48.2 C49.2 C50.2 C51.2 C52.2 C53.2 C54.2 C55.2 C57.2 C58.2 C59.2 C61.2 C64.2 C65.2 C66.2 C67.2 C91.2 C93.2 C97.2 C125.2 C148.2 C159.2 C194.2 C206.1 C207.2 C208.1 C211.1 C213.1 C217.2 C218.2 C219.2 C220.2 C221.1 C222.1 C223.2 C224.2 C225.1 C226.2 C227.2 C228.2 C230.2 C231.2 C232.1 C233.2 C234.2 C235.2 C236.2 C237.2 C238.2 C239.2 C240.2 C241.2 C242.2 C243.2 C244.2 C245.2 C246.2 C247.2 C248.2 C249.2 C250.2 C251.2 C253.2 C254.2 C256.2 C257.2 C259.2 C261.2 C262.2 C263.2 C264.2 C273.2 D16.1(Cathode) D17.2(ANODE) D19.2(ANODE) FB13.1 J11.2 J11.3 J12.2 J13.5(GND) J14.17 J14.18 J14.29 J14.30 J15.8(GND) J15.10(GND) J15.12(GND) J15.16(GND) J15.20(GND) MH1.1 MH2.1 MH3.1 MH4.1 R14.1(P1) R17.1(P1) R66.1 R82.1(P1) R102.1(P1) R115.1(P1) R137.1(P1) R176.1(P1) R185.1(P1) R187.1(P1) R188.1 R193.1 R222.1(P1) R223.1(P1) R229.2(P2) R244.2(P2) S1.1(A1) TP18.1 TP19.1 U6.1(A0) U6.2(A1) U6.3(A2) U6.4(VSS) U10.3(GND) U13.4(GND) U17.4(GND) U18.1(GND.1) U18.5(GND.2) U18.10(AGND) U18.11(GND.3) U18.13(TEST) U18.15(GND.4) U18.25(GND.5) U18.32(ACBUS5) U18.35(GND.6) U18.47(GND.7) U18.51(GND.8) U19.2(GND) U19.5(GS1) U20.3(GND) U21.6(GND) U22.15(GNDIO) U22.17(REFGND) U22.20(OSC32KIN) U22.30(VFB3) U22.34(GND1) U22.43(GND2) U22.PPAD(GNDP) U23.4(GND) U30.2(GND) U31.7(A2) U31.8(~{G}) U31.9(A0) U31.10(A1) U31.16(GND) U32.3(GND) U32.6(GND) U33.2(GND) U35.28(GND) U35.TH_PD(THRM) ; also on sheet 1 2 3 4 5 6 7 8 9
GND_EARTH: FB13.2 J13.S1 J13.S2 J13.S3 J13.S4 S1.3(A3) ; also on sheet 1
GND_OSC0: C99.2 C100.2 U14.V11(VSS_OSC) ; also on sheet 9
GND_OSC1: C40.1 C42.1 U14.A5(VSS_RTC)
GNDA_ADC: C33.2 C34.2 C35.2 J14.38 J14.39 J14.40 U14.A9(VREFN) ; also on sheet 9
V3_3D: C8.1 C44.1 C46.1 C91.1 C93.1 C207.1 C218.1 C219.1 C220.1 C230.1 C231.1 C232.2 C236.1 C238.1 FB9.1 FB10.1 FB12.1 J15.5(TVDD) R24.2(P2) R25.2(P2) R75.2(P2) R141.2(P2) R199.2(P2) R200.2(P2) R205.2(P2) R206.2(P2) R210.2(P2) R211.2(P2) U6.8(VCC) U10.5(VCC) U17.8(VCC) U18.20(VCCIO.1) U18.28(ACBUS2) U18.31(VCCIO.2) U18.42(VCCIO.3) U18.56(VCCIO.4) U19.1(GS0) U19.4(VDD) U31.1(VCC) U32.4(OUT) U33.6(VCC) ; also on sheet 1 2 3 4 5 6 8
V5_0D: C48.1 C57.1 C58.1 C59.1 C61.1 C64.1 C66.1 C97.1 C217.1 C226.1 C227.1 C228.1 C251.1 C257.1 J14.27 J14.28 L3.2 R67.2(P2) R132.1(P1) R133.1(P1) R136.1(P1) R140.1(P1) R143.1(P1) R151.1(P1) R155.1(P1) R173.1(P1) U22.3(VCC3) U22.6(VCC6) U22.13(VCCIO) U22.23(VCC5) U22.27(VBACKUP) U22.28(VCC7) U22.36(VCC1) U22.41(VCC2) U22.47(VCC4) U30.1(IN) U30.3(EN) U32.2(IN) ; also on sheet 1 8
V5_0VOP: C55.1 C234.1 C240.1 U20.5(VCC) U35.15(5VOP)
V24_0HVS: C233.1 C242.1 C243.1 C248.1 C249.1 C273.1 D19.1(CATHODE) F1.2 J14.2 J14.4 J14.6 J14.8 J14.10 J14.12 J14.14 J14.16 R227.2(P2) R243.1(P1) U21.7(VIN)
V24_IN: D18.2(ANODE) J11.1 J12.1 ; also on sheet 1
VDD1_SMPS: R86.1(P1) ; also on sheet 9
VDD2_SMPS: R73.1(P1) ; also on sheet 9
VDD_1V8FT: C206.2 C208.2 C224.1 C225.2 U18.12(VCORE.1) U18.37(VCORE.2) U18.49(VREGOUT) U18.64(VCORE.3)
VDD_FTREGIN: FB9.2 U18.50(VREGIN)
VDD_FTVPHY: C213.2 FB10.2 U18.4(VPHY)
VDD_FTVPLL: C221.2 FB12.2 U18.9(VPLL)
VDDA_ADC: R60.2(P2) ; also on sheet 9
VDDS_DDR: R85.1(P1) ; also on sheet 7 9
AIN1: J14.31 U14.C7(AIN1)
AIN2: J14.33 U14.B7(AIN2)
AIN3: J14.35 U14.A7(AIN3)
AIN4: J14.37 U14.C8(AIN4)
AIN5: J14.32 U14.B8(AIN5)
AIN6: J14.34 U14.A8(AIN6)
AIN7: J14.36 U14.C9(AIN7)
AM335X_OSC0_IN: C100.1 R172.2(P2) U14.V10(XTALIN) Y3.3 ; also on sheet 3
AM335X_REFCLK_RMII1: U14.H18(MII1_REFCLK) ; also on sheet 3
AM335X_REFCLK_RMII2: U14.H16(MII1_COL) ; also on sheet 2
boot: C56.1 U21.1(BOOT)
DDR_A0: U14.F3(DDR_A0) ; also on sheet 7
DDR_A1: U14.H1(DDR_A1) ; also on sheet 7
DDR_A2: U14.E4(DDR_A2) ; also on sheet 7
DDR_A3: U14.C3(DDR_A3) ; also on sheet 7
DDR_A4: U14.C2(DDR_A4) ; also on sheet 7
DDR_A5: U14.B1(DDR_A5) ; also on sheet 7
DDR_A6: U14.D5(DDR_A6) ; also on sheet 7
DDR_A7: U14.E2(DDR_A7) ; also on sheet 7
DDR_A8: U14.D4(DDR_A8) ; also on sheet 7
DDR_A9: U14.C1(DDR_A9) ; also on sheet 7
DDR_A10: U14.F4(DDR_A10) ; also on sheet 7
DDR_A11: U14.F2(DDR_A11) ; also on sheet 7
DDR_A12: U14.E3(DDR_A12) ; also on sheet 7
DDR_A13: U14.H3(DDR_A13) ; also on sheet 7
DDR_A14: U14.H4(DDR_A14) ; also on sheet 7
DDR_BA0: U14.C4(DDR_BA0) ; also on sheet 7
DDR_BA1: U14.E1(DDR_BA1) ; also on sheet 7
DDR_BA2: U14.B3(DDR_BA2) ; also on sheet 7
DDR_CASn: U14.F1(DDR_CASn) ; also on sheet 7
DDR_CKE: U14.G3(DDR_CKE) ; also on sheet 7
DDR_CLK: U14.D2(DDR_CK) ; also on sheet 7
DDR_CLKn: U14.D1(DDR_CKn) ; also on sheet 7
DDR_CSn: U14.H2(DDR_CSn0) ; also on sheet 7
DDR_D0: U14.M3(DDR_D0) ; also on sheet 7
DDR_D1: U14.M4(DDR_D1) ; also on sheet 7
DDR_D2: U14.N1(DDR_D2) ; also on sheet 7
DDR_D3: U14.N2(DDR_D3) ; also on sheet 7
DDR_D4: U14.N3(DDR_D4) ; also on sheet 7
DDR_D5: U14.N4(DDR_D5) ; also on sheet 7
DDR_D6: U14.P3(DDR_D6) ; also on sheet 7
DDR_D7: U14.P4(DDR_D7) ; also on sheet 7
DDR_D8: U14.J1(DDR_D8) ; also on sheet 7
DDR_D9: U14.K1(DDR_D9) ; also on sheet 7
DDR_D10: U14.K2(DDR_D10) ; also on sheet 7
DDR_D11: U14.K3(DDR_D11) ; also on sheet 7
DDR_D12: U14.K4(DDR_D12) ; also on sheet 7
DDR_D13: U14.L3(DDR_D13) ; also on sheet 7
DDR_D14: U14.L4(DDR_D14) ; also on sheet 7
DDR_D15: U14.M1(DDR_D15) ; also on sheet 7
DDR_DQM0: U14.M2(DDR_DQM0) ; also on sheet 7
DDR_DQM1: U14.J2(DDR_DQM1) ; also on sheet 7
DDR_DQS0: U14.P1(DDR_DQS0) ; also on sheet 7
DDR_DQS1: U14.L1(DDR_DQS1) ; also on sheet 7
DDR_DQSN0: U14.P2(DDR_DQSn0) ; also on sheet 7
DDR_DQSN1: U14.L2(DDR_DQSn1) ; also on sheet 7
DDR_ODT: U14.G1(DDR_ODT) ; also on sheet 7
DDR_RASn: U14.G4(DDR_RASn) ; also on sheet 7
DDR_RESETN: U14.G2(DDR_RESETn) ; also on sheet 7
DDR_VREF: C159.1 U14.J4(DDR_VREF) ; also on sheet 7
DDR_VTP: R185.2(P2) U14.J3(DDR_VTP)
DDR_VTT_EN: U14.F16(USB0_DRVVBUS) ; also on sheet 7
DDR_WEn: U14.B2(DDR_WEn) ; also on sheet 7
DRAIN0: D15.1(Cathode) J14.19 U31.3(DRAIN0)
DRAIN1: D14.1(Cathode) J14.20 U31.4(DRAIN1)
DRAIN2: D12.1(Cathode) J14.21 U31.5(DRAIN2)
DRAIN3: D10.1(Cathode) J14.22 U31.6(DRAIN3)
DRAIN4: D9.1(Cathode) J14.23 U31.11(DRAIN4)
DRAIN5: D8.1(Cathode) J14.24 U31.12(DRAIN5)
DRAIN6: D7.1(Cathode) J14.25 U31.13(DRAIN6)
DRAIN7: D6.1(Cathode) J14.26 U31.14(DRAIN7)
EMU2_GPIO0_19: R35.2(P2) U14.A15(XDMA_EVENT_INTR0) ; also on sheet 8
EMU2R: J15.17(EMU2) R35.1(P1)
EMU3_GPIO0_20: R26.1(P1) U14.D14(XDMA_EVENT_INTR1) ; also on sheet 8
EMU3R: J15.18(EMU3) R26.2(P2)
EMU4: R36.2(P2) U14.A14(MCASP0_AHCLKX) ; also on sheet 1
EMU4R: J15.19(EMU4) R36.1(P1)
EMU_RSTn: C13.1 J15.15(SRST) R20.1(P1)
F_ADBUS0: R209.2(P2) U18.16(ADBUS0)
F_ADBUS1: R192.2(P2) U18.17(ADBUS1)
F_ADBUS2: R190.2(P2) U18.18(ADBUS2)
F_ADBUS3: R194.2(P2) U18.19(ADBUS3)
F_ADBUS4: R201.2(P2) U18.21(ADBUS4)
F_ADBUS5: R203.2(P2) U18.26(ACBUS0)
F_ADBUS6: R202.2(P2) U18.23(ADBUS6)
F_ADBUS7: R204.2(P2) U18.30(ACBUS4)
F_EECS: R210.1(P1) U18.63(EECS) U33.5(CS)
F_EEDATA: R207.1(P1) U18.61(EEDATA) U33.3(DIN)
F_EEDOUT: R207.2(P2) R211.1(P1) U33.1(DOUT)
F_EESK: R206.1(P1) U18.62(EESK) U33.4(SK)
FET_nOE: U14.C18(ECAP0_IN_PWM0_OUT) ; also on sheet 8
FT_REF: R193.2 U18.6(REF)
FT_RESETn: R205.1(P1) U18.14(RESET#)
FT_SRESET: R137.2(P2) R141.1(P1) R203.1(P1) U10.2(A)
GPIO2-5: U14.T6(GPMC_BEn0_CLE) ; also on sheet 3
GPIO2_12: U14.T3(LCD_DATA6) ; also on sheet 6 8
GPIO2_13: U14.T4(LCD_DATA7) ; also on sheet 6 8
GPIO3_18: R244.1(P1) U14.B12(MCASP0_ACLKR) U35.26(~{LD}) ; also on sheet 1
GPIO3_19: U14.C13(MCASP0_FSR) ; also on sheet 1 5
GPIO3_20: U14.D13(MCASP0_AXR1) ; also on sheet 1
GPMC_AD0: U14.U7(GPMC_AD0) ; also on sheet 1 6
GPMC_AD1: U14.V7(GPMC_AD1) ; also on sheet 1 6
GPMC_AD2: U14.R8(GPMC_AD2) ; also on sheet 1 6
GPMC_AD3: U14.T8(GPMC_AD3) ; also on sheet 1 6
GPMC_AD4: U14.U8(GPMC_AD4) ; also on sheet 1 6
GPMC_AD5: U14.V8(GPMC_AD5) ; also on sheet 1 6
GPMC_AD6: U14.R9(GPMC_AD6) ; also on sheet 1 6
GPMC_AD7: U14.T9(GPMC_AD7) ; also on sheet 1 6
GPMC_AD8: U14.U10(GPMC_AD8) ; also on sheet 1 6
GPMC_AD9: U14.T10(GPMC_AD9) ; also on sheet 1 6
GPMC_AD10: U14.T11(GPMC_AD10) ; also on sheet 1 6
GPMC_AD11: U14.U12(GPMC_AD11) ; also on sheet 1 6
GPMC_AD12: U14.T12(GPMC_AD12) ; also on sheet 1 6
GPMC_AD13: U14.R12(GPMC_AD13) ; also on sheet 1 6
GPMC_AD14: U14.V13(GPMC_AD14) ; also on sheet 1 6
GPMC_AD15: U14.U13(GPMC_AD15) ; also on sheet 1 6
GPMC_ADVn_ALE: U14.R7(GPMC_ADVn_ALE) ; also on sheet 1 6
GPMC_CSn0: U14.V6(GPMC_CSn0) ; also on sheet 6
GPMC_CSn2: U14.V9(GPMC_CSn2) ; also on sheet 1
GPMC_NOR_A1: R102.2(P2) U14.U5(LCD_VSYNC) ; also on sheet 6
GPMC_NOR_A2: R115.2(P2) U14.R5(LCD_HSYNC) ; also on sheet 6
GPMC_OEn_REn: U14.T7(GPMC_OEn_REn) ; also on sheet 1 6
GPMC_WEn: U14.U6(GPMC_WEn) ; also on sheet 1 6
I2C0_SCL: R69.2(P2) R196.1(P1) U6.6(SCL) U14.C16(I2C0_SCL) U31.15(SCL) ; also on sheet 1 3
I2C0_SDA: R61.1(P1) R72.2(P2) U6.5(SDA) U14.C17(I2C0_SDA) U31.2(SDA) ; also on sheet 1 3
INDUS_INPUT0: J14.1 R226.1(P1)
INDUS_INPUT1: J14.3 R84.1(P1)
INDUS_INPUT2: J14.5 R83.1(P1)
INDUS_INPUT3: J14.7 R81.1(P1)
INDUS_INPUT4: J14.9 R80.1(P1)
INDUS_INPUT5: J14.11 R79.1(P1)
INDUS_INPUT6: J14.13 R74.1(P1)
INDUS_INPUT7: J14.15 R68.1(P1) R243.2(P2)
INDUS_INPUTSO: U20.2(A) U35.23(SOP)
JTAG_EMU0: J15.13(EMU0) R25.1(P1) R202.1(P1) U14.C14(EMU0///////GPIO3_7)
JTAG_EMU1: J15.14(EMU1) R24.1(P1) R204.1(P1) U14.B14(EMU1///////GPIO3_8)
JTAG_TCK: R22.2(P2) R23.2(P2) R209.1(P1) U14.A12(TCK)
JTAG_TDI: J15.3(TDI) R192.1(P1) U14.B11(TDI)
JTAG_TDO: J15.7(TDO) R190.1(P1) U14.A11(TDO)
JTAG_TMS: J15.1(TMS) R194.1(P1) U14.C11(TMS)
JTAG_TRSTn: J15.2(TRSTn) R14.2(P2) R201.1(P1) U14.B10(TRSTn)
LATCH0_IN: U14.D18(UART1_CTSn) ; also on sheet 1
LATCH1_IN: U14.D17(UART1_RTSn) ; also on sheet 1
LCD_BST_CONV_CTL: U14.F15(USB1_DRVVBUS) ; also on sheet 1
LED_1: U14.K15(MII1_TXD2) ; also on sheet 8
LED_2: U14.J18(MII1_TXD3) ; also on sheet 8
LED_3: U14.K18(MII1_TXCLK) ; also on sheet 8
LED_4: U14.U9(GPMC_CSn1) ; also on sheet 8
MDIO_CLK: U14.M18(MDIO_CLK) ; also on sheet 4
MDIO_DATA: U14.M17(MDIO_DATA) ; also on sheet 4
MMC0_CLK: R58.1(P1) ; also on sheet 1
MMC0_CMD: U14.G18(MMC0_CMD) ; also on sheet 1
MMC0_DAT0: U14.G16(MMC0_DAT0) ; also on sheet 1
MMC0_DAT1: U14.G15(MMC0_DAT1) ; also on sheet 1
MMC0_DAT2: U14.F18(MMC0_DAT2) ; also on sheet 1
MMC0_DAT3: U14.F17(MMC0_DAT3) ; also on sheet 1
MUX_MII_CTL1: U14.L18(MII1_RXCLK) ; also on sheet 4
OSC0_OUT: R156.1(P1) U14.U11(XTALOUT)
OSC0_OUT1: C99.1 R156.2(P2) R172.1(P1) Y3.1
OSC1_IN: C42.2 U14.A6(RTC_XTALIN) Y4.4
OSC1_OUT: R64.1(P1) U14.A4(RTC_XTALOUT)
OSC1_OUT1: C40.2 R64.2(P2) Y4.1
ph: C56.2 D17.1(CATHODE) L3.1 U21.8(PH)
PMIC_I2C_SCL: R69.1(P1) R70.1(P1) U22.9(SCL_SCK)
PMIC_I2C_SDA: R71.1(P1) R72.1(P1) U22.8(SDA_SDI)
PMIC_INTn: TP27.1 U22.45(INT1)
PMIC_PWR_EN: U14.C6(PMIC_POWER_EN) U22.1(PWRHOLD)
PMIC_RESETOUTn: C194.1 R187.2(P2) U14.B15(PWRONRSTn) U22.40(nRESPWRON)
PMIC_SLEEP: TP31.1 U22.37(SLEEP)
PMICSR_I2C_SCL: TP29.1 U22.11(SCLSR_EN1)
PMICSR_I2C_SDA: TP28.1 U22.10(SDASR_EN2)
PR1_MDIO_DATA: U14.T13(GPMC_CSn3) ; also on sheet 4
PR1_MDIO_MDCLK: U14.V12(GPMC_CLK) ; also on sheet 4
PR1_MII0_RXLINK_SPEED: U14.V2(CD_DATA12) ; also on sheet 8
PR1_MII1_CLK: U14.U16(GPMC_A9) ; also on sheet 2
PR1_MII1_COL_RMII2_CRS_DV: U14.T17(GPMC_WAIT0) ; also on sheet 4
PR1_MII1_CRS: U14.R6(LCD_AC_BIAS_EN) ; also on sheet 2 4
PR1_MII1_RXD0: U14.V16(GPMC_A8) ; also on sheet 2 4
PR1_MII1_RXD1: U14.T15(GPMC_A7) ; also on sheet 2 4
PR1_MII1_RXD2: U14.U15(GPMC_A6) ; also on sheet 2
PR1_MII1_RXD3_RMII2_TXD0: U14.V15(GPMC_A5) ; also on sheet 4
PR1_MII1_RXDV_RMII2_RXD1: U14.T16(GPMC_A10) ; also on sheet 4
PR1_MII1_RXER_RMII2_RXD0: U14.V17(GPMC_A11) ; also on sheet 4
PR1_MII1_TXCLK_RMII2_TXEN: U14.R13(GPMC_A0) ; also on sheet 4
PR1_MII1_TXD0_RMII2_TXD1: U14.R14(GPMC_A4) ; also on sheet 4
PR1_MII1_TXD1: U14.T14(GPMC_A3) ; also on sheet 2 4
PR1_MII1_TXD2: U14.U14(GPMC_A2) ; also on sheet 2
PR1_MII1_TXD3: U14.V14(GPMC_A1) ; also on sheet 2
PR1_MII1_TXEN_RMII2_RXERR: U14.U17(GPMC_WPn) ; also on sheet 4
PR1_MII_CTL: U14.J17(MII1_RXDV) ; also on sheet 8
PRUETH0_CRS: U14.H17(MII1_CRS) U14.V5(LCD_PCLK) ; also on sheet 3
PRUETH0_RXCLK: U14.V4(LCD_DATA14) ; also on sheet 3 8
PRUETH0_RXD0: U14.M16(MII1_RXD0) U14.U4(LCD_DATA11) ; also on sheet 3 8
PRUETH0_RXD1: U14.L15(MII1_RXD1) U14.U3(LCD_DATA10) ; also on sheet 3 8
PRUETH0_RXD2: U14.U2(LCD_DATA9) ; also on sheet 3 8
PRUETH0_RXD3: U14.U1(LCD_DATA8) ; also on sheet 3 8
PRUETH0_RXDV: U14.T5(LCD_DATA15) ; also on sheet 3 8
PRUETH0_RXERR: U14.J15(MII1_RXERR) ; also on sheet 3 4
PRUETH0_RXERR_COL_PROC: U14.V3(LCD_DATA13) ; also on sheet 8
PRUETH0_TXCLK: U14.R1(LCD_DATA0) ; also on sheet 3 8
PRUETH0_TXD0: U14.K17(MII1_TXD0) U14.T2(LCD_DATA5) ; also on sheet 3 8
PRUETH0_TXD1: U14.K16(MII1_TXD1) U14.T1(LCD_DATA4) ; also on sheet 3 8
PRUETH0_TXD2: U14.R4(LCD_DATA3) ; also on sheet 3 8
PRUETH0_TXD3: U14.R3(LCD_DATA2) ; also on sheet 3 8
PRUETH0_TXEN: U14.J16(MII1_TXEN) U14.R2(LCD_DATA1) ; also on sheet 3 8
PRUETH1_SPEEDLED: U14.U18(GPMC_BEn1) ; also on sheet 2
PWR_SWIO: L5.1 U22.14(SWIO)
PWR_VAUX1: C53.1 R214.1(P1) U22.46(VAUX1)
PWR_VAUX2: C237.1 R213.1(P1) U22.48(VAUX2)
PWR_VAUX33: C51.1 R78.1(P1) R216.2(P2) U22.4(VAUX33)
PWR_VDAC: C244.1 R77.1(P1) U22.22(VDAC)
PWR_VDD1_SMPS: C67.1 L7.2 R86.2(P2) U22.32(VFB1)
PWR_VDD2_SMPS: C54.1 L4.2 R73.2(P2) U22.44(VFB2)
PWR_VDDIO: R78.2(P2) U22.12(VDDIO)
PWR_VDDS_DDR: C65.1 L5.2 R85.2(P2) U22.16(VFBIO)
PWR_VDIG1: C49.1 R218.2(P2) U22.7(VDIG1)
PWR_VDIG2: C50.1 R217.2(P2) U22.5(VDIG2)
PWR_VMMC: C52.1 R215.2(P2) U22.2(VMMC)
PWR_VPLL: C245.1 R76.1(P1) U22.24(VPLL)
PWRON: TP30.1 U22.33(PWRON)
RTC_PORZ: R176.2(P2) U13.7(2Y) U14.B5(RTC_PWRONRSTn)
RTCK: J15.9(TCKRTN) R22.1(P1)
sense: R66.2 R67.1(P1) U21.4(VSNS)
SPI0_CS0: U14.A16(SPI0_CS0) U17.1(~{CS})
SPI0_CS1: U14.C15(SPI0_CS1) U35.24(~{CE})
SPI0_D0: R75.1(P1) TP39.1 U14.B17(SPI0_D0) U17.2(DO) U20.4(Y)
SPI0_D1: TP38.1 U14.B16(SPI0_D1) U17.5(DI)
SPI0_SCLK: U14.A17(SPI0_SCLK) U17.6(CLK) U35.25(CLK)
SPI1_CS0: U14.C12(MCASP0_AHCLKR) ; also on sheet 1
SPI1_D0: U14.B13(MCASP0_FSX) ; also on sheet 1
SPI1_D1: U14.D12(MCASP0_AXR0) ; also on sheet 1
SPI1_SCLK: U14.A13(MCASP0_ACLKX) ; also on sheet 1
SW3: U22.31(SW3)
SYS_RESETn: R20.2(P2) R142.1(P1) R197.1(P1) R198.2(P2) U14.A10(WARMRSTn) ; also on sheet 1 3 6
SYS_WARMRESETn: C235.1 R198.1(P1) S1.2(A2)
TCK: J15.11(TCK) R23.1(P1)
TDIS: J15.4(TDIS) R17.2(P2)
TEMP_SENSE: U14.B6(AIN0) U19.3(OUT)
UART0_RXD: U14.E15(UART0_RXD) ; also on sheet 5
UART0_TXD: U14.E16(UART0_TXD) ; also on sheet 5
UART1_RXD: U14.D16(UART1_RXD) ; also on sheet 5
UART1_TXD: U14.D15(UART1_TXD) ; also on sheet 5
UART3_RXD: U14.L17(MII1_RXD3) U18.38(BDBUS0)
UART3_TXD: U14.L16(MII1_RXD2) U18.39(BDBUS1)
UART4_RXD_SYNC0_OUT: U14.E18(UART0_CTSn) ; also on sheet 1
UART4_TXD_SYNC1_OUT: U14.E17(UART0_RTSn) ; also on sheet 1
USB_DC: C263.1 C264.1 J13.1(VBUS) R189.2 U23.6(VBUS)
USBDM: J13.2(DM) L6.3 U23.2(D-)
USBDM_FT: L6.2 U18.7(DM)
USBDP: J13.3(DP) L6.4 U23.1(D+)
USBDP_FT: L6.1 U18.8(DP)
VAUX1: R214.2(P2) ; also on sheet 3 9
VAUX2: R61.2(P2) R70.2(P2) R71.2(P2) R196.2(P2) R197.2(P2) R213.2(P2) U32.1(EN) ; also on sheet 8 9
VAUX33: R208.2(P2) R216.1(P1) ; also on sheet 7 9
VDAC: R77.2(P2) ; also on sheet 9
VDIG1: R218.1(P1) TP26.1
VDIG2: R217.1(P1) ; also on sheet 9
VMMC: R215.1(P1) ; also on sheet 1 9
VPLL: R76.2(P2) ; also on sheet 9
VPMIC_VRTC: C261.1 R228.2(P2) U22.29(VRTC)
VREFP_ADC: C33.1 C34.1 C35.1 R60.1(P1) U14.B9(VREFP)
VRTC: C125.1 C223.1 U13.5(2A) U13.6(2B) U13.8(VCC) U30.5(OUT) ; also on sheet 9
VRTC_DET: R177.1(P1) U13.3(2Y)
VRTC_DETB: C148.1 R177.2(P2) U13.1(2A) U13.2(2B)
XTIN: C211.2 U18.2(XTIN) Y2.3(X3)
XTOUT: C222.2 U18.3(XTOUT) Y2.1(X1)
N16839102: C262.1 R227.1(P1) U35.14(VCC)
N16839202: R82.2(P2) U35.13(RLIM)
N16839209: R223.2(P2) U35.2(DB1)
N16839216: R222.2(P2) U35.1(DB0)
N16844016: D15.2(Anode) R173.2(P2)
N16844076: D14.2(Anode) R155.2(P2)
N16844150: D12.2(Anode) R151.2(P2)
N16844168: D10.2(Anode) R143.2(P2)
N16844256: D9.2(Anode) R140.2(P2)
N16844274: D8.2(Anode) R136.2(P2)
N16844366: D7.2(Anode) R133.2(P2)
N16844384: D6.2(Anode) R132.2(P2)
N17107785: C254.1 U22.18(VREF)
N17123334: L7.1 U22.35(SW1)
N17123833: L4.1 U22.42(SW2)
N19577113: R229.1(P1) U22.26(BOOT0)
N19577116: R228.1(P1) U22.19(BOOT1)
N20364263: TP23.1 U14.C5(EXT_WAKEUP)
N21451174: R199.1(P1) U17.3(~{WP})
N21451189: R200.1(P1) U17.7(~{HOLD})
N21620210: C259.1 R226.2(P2) U35.3(IP0)
N21620213: C256.1 R84.2(P2) U35.5(IP1)
N21620216: C253.1 R83.2(P2) U35.7(IP2)
N21620219: C250.1 R81.2(P2) U35.9(IP3)
N21620222: C247.1 R80.2(P2) U35.11(IP4)
N21620225: C246.1 R79.2(P2) U35.18(IP5)
N21620228: C241.1 R74.2(P2) U35.20(IP6)
N21620231: C239.1 R68.2(P2) U35.22(IP7)
N22371955: C43.1 U32.5(FB)
N27955689: R188.2 R189.1 U18.59(BCBUS7)
N27956453: R142.2(P2) U10.4(Y)
N28614111: D18.1(CATHODE) F1.1
N28629254: D16.2(Anode) R208.1(P1)
N28737675: R58.2(P2) U14.G17(MMC0_CLK)

Not connected (* = marked no-connect by the designer): J13 4(ID)*; J15 6(NC)*; U6 7(WP)*; U10 1(NC)*; U14 B18(NMIn)* D3(DDR_A15)* M15(USB0_CE)* N17(USB0_DP)* N18(USB0_DM)* P15(USB0_VBUS)* P16(USB0_ID)* P17(USB1_ID)* P18(USB1_CE)* R17(USB1_DP)* R18(USB1_DM)* T18(USB1_VBUS)*; U18 22(ADBUS5)* 24(ADBUS7)* 27(ACBUS1)* 29(ACBUS3)* 33(ACBUS6)* 34(ACBUS7)* 36(SUSPEND#)* 40(BDBUS2)* 41(BDBUS3)* 43(BDBUS4)* 44(BDBUS5)* 45(BDBUS6)* 46(BDBUS7)* 48(BCBUS0)* 52(BCBUS1)* 53(BCBUS2)* 54(BCBUS3)* 55(BCBUS4)* 57(BCBUS5)* 58(BCBUS6)* 60(PWREN#)*; U20 1(NC)*; U21 2(NC1)* 3(NC2)* 5(ENA)*; U22 21(OSC32KOUT)* 25(TESTV)* 38(CLK32KOUT)* 39(GPIO_CKSYNC)*; U23 3(ID)* 5(NC)*; U30 4(NR)*; U35 4(RE0)* 6(RE1)* 8(RE2)* 10(RE3)* 12(RE4)* 16(TOK)* 17(RE5)* 19(RE6)* 21(RE7)* 27(SIP)*; Y2 2(X2)* 4(X4)*; Y3 2(NC0)* 4(NC1)*; Y4 2* 3*

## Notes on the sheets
sheet 10
- AM335X
- TEMPERATURE SENSOR
- SPI FLASH
- BOARD ID EEPROM
- Variable  & MAC Memory
- 256KX8
sheet 11
- AM335X
- RTC POWER ON RESET
- WARM RESET SWITCH
sheet 12
- Main Power Input
- 24V to 5V DC - DC CONVERTER
- VRTC REGULATOR
- Power Management IC
- Power On LED
- MOUNT HOLES
- GND PROBING POINTS
- LDO for V3_3D
- 1.5A
sheet 13
- AM335X_ICE Board
- -See the Hardware Implementation Document for design details
- -See the Hardware User Guide for board details
- -See the PCB Build Specification for PCB Details
sheet 14
- USB TO UART / JTAG
- Micro USB-AB
- 10X2 JTAG HEADER
- BREAK UP RESISTORS
- FT2232L RESET
sheet 15
- DIGITAL INPUTS
- DIGITAL OUTPUTS
- I/O EXPANSION HEADER
